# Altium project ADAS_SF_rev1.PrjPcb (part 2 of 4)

## Sheet ADAS_SF_Power_Buck_3V3_1V8_1V1.SchDoc
size 431 x 279 mm; Date: Not shown in title block; ApprovedBy: Not shown in title block; CheckedBy: Not shown in title block; Author: Not shown in title block; CompanyName: Not shown in title block; Engineer: Not shown in title block; Organization: Not shown in title block; Address1: Not shown in title block; Address2: Not shown in title block; Address3: Not shown in title block; Address4: Not shown in title block; DocumentNumber: 1; Revision: Use project parameter SCH_Rev; SheetNumber: 5; SheetTotal: 15; PageSetup: Record=PageOptions¦CenterHorizontal=True¦CenterVertical=True¦PrintScale=1.00¦XCorrection=1.00¦YCorrection=1.00¦PrintKind=0¦BorderSize=5000000¦LeftOffset=0¦BottomOffset=0¦Orientation=2¦PaperLength=1000¦PaperWidth=1000¦Scale=100¦PaperSource=15¦PrintQuality=600¦MediaType=1¦DitherType=10¦PaperKind=Letter¦PrintScaleMode=1
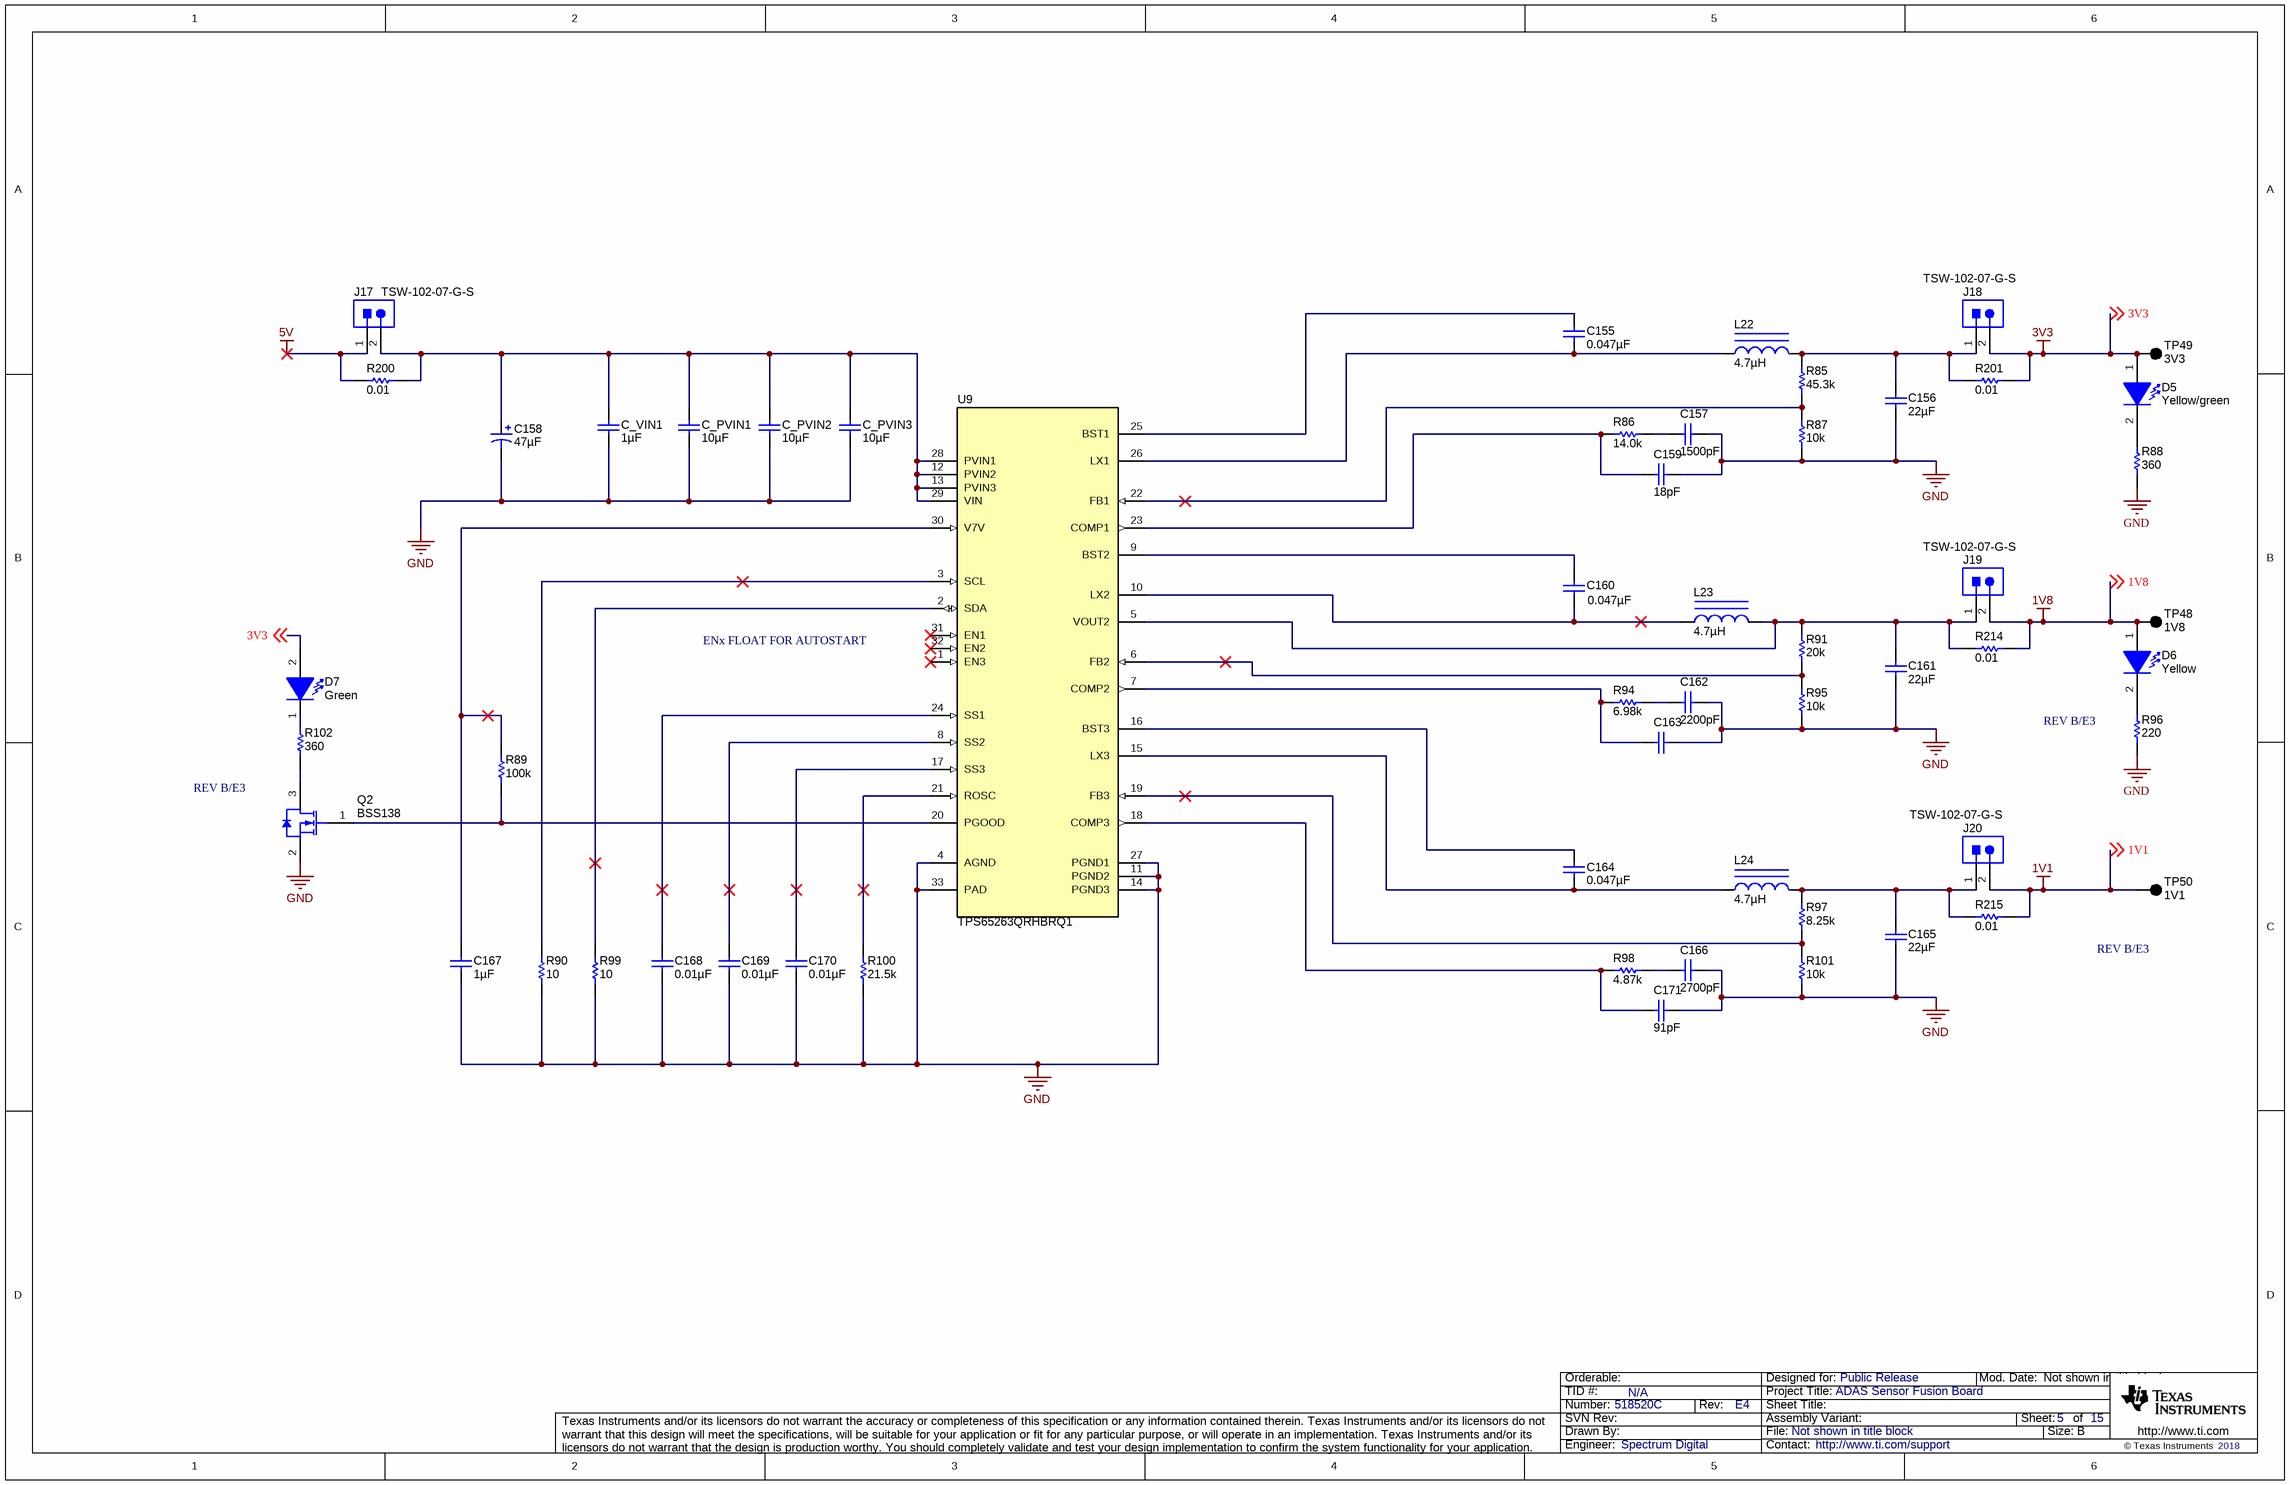
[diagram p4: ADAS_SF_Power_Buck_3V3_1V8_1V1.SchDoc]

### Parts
C155  ValueDisplayed: 0.047µF  [0402]  (hidden comment: GRM155R60J473KA01D)
C156  ValueDisplayed: 22µF  [0603]  (hidden comment: GRM188R61A226ME15D)
C157  ValueDisplayed: 1500pF  [0402]  (hidden comment: GRM155R71H152KA01D)
C158  ValueDisplayed: 47µF  [SM_RADIAL_C]  (hidden comment: EEE-FC0J470R)
C159  ValueDisplayed: 18pF  [0402]  (hidden comment: GRM1555C1H180JA01D)
C160  ValueDisplayed: 0.047µF  [0402]  (hidden comment: GRM155R60J473KA01D)
C161  ValueDisplayed: 22µF  [0603]  (hidden comment: GRM188R61A226ME15D)
C162  ValueDisplayed: 2200pF  [0402]  (hidden comment: GRM155R61A222KA01D)
C163  GRM1555C1H510JA01D  [0402]  (value not drawn)
C164  ValueDisplayed: 0.047µF  [0402]  (hidden comment: GRM155R60J473KA01D)
C165  ValueDisplayed: 22µF  [0603]  (hidden comment: GRM188R61A226ME15D)
C166  ValueDisplayed: 2700pF  [0402]  (hidden comment: GRM155R71H272KA01D)
C167  ValueDisplayed: 1µF  [0402]  (hidden comment: C1005JB1V105K050BC)
C168  ValueDisplayed: 0.01µF  [0402]  (hidden comment: GRM155R71C103KA01D)
C169  ValueDisplayed: 0.01µF  [0402]  (hidden comment: GRM155R71C103KA01D)
C170  ValueDisplayed: 0.01µF  [0402]  (hidden comment: GRM155R71C103KA01D)
C171  ValueDisplayed: 91pF  [0402]  (hidden comment: GRM1555C1H910JA01D)
C_PVIN1  ValueDisplayed: 10µF  [0603]  (hidden comment: GRT188C81A106ME13D)
C_PVIN2  ValueDisplayed: 10µF  [0603]  (hidden comment: GRT188C81A106ME13D)
C_PVIN3  ValueDisplayed: 10µF  [0603]  (hidden comment: GRT188C81A106ME13D)
C_VIN1  ValueDisplayed: 1µF  [0402]  (hidden comment: C1005JB1V105K050BC)
D5  value Yellow/green  [SML-P1_YELLOW-GREEN]  (hidden comment: SML-P12MTT86)
D6  value Yellow  [LED_SMLP12_Yellow]  (hidden comment: SML-P12YTT86)
D7  value Green  [SML-P1_GREEN]  (hidden comment: SML-P12PTT86)
J17  TSW-102-07-G-S  [TSW-102-07-G-S]
J18  TSW-102-07-G-S  [TSW-102-07-G-S]
J19  TSW-102-07-G-S  [TSW-102-07-G-S]
J20  TSW-102-07-G-S  [TSW-102-07-G-S]
L22  ValueDisplayed: 4.7µH  [SDR0805]  (hidden comment: SDR0805-4R7ML)
L23  ValueDisplayed: 4.7µH  [SDR0805]  (hidden comment: SDR0805-4R7ML)
L24  ValueDisplayed: 4.7µH  [SDR0805]  (hidden comment: SDR0805-4R7ML)
Q2  BSS138  [SOT-23]
R85  ValueDisplayed: 45.3k  [0402]  (hidden comment: CRCW040245K3FKED)
R86  ValueDisplayed: 14.0k  [0402]  (hidden comment: CRCW040214K0FKED)
R87  ValueDisplayed: 10k  [0402]  (hidden comment: CRCW040210K0JNED)
R88  ValueDisplayed: 360  [0402]  (hidden comment: CRCW0402360RJNED)
R89  ValueDisplayed: 100k  [0402]  (hidden comment: CRCW0402100KDHEDP)
R90  ValueDisplayed: 10  [0402]  (hidden comment: CRCW040210R0JNED)
R91  ValueDisplayed: 20k  [0402]  (hidden comment: CRCW040220K0JNED)
R94  ValueDisplayed: 6.98k  [0402]  (hidden comment: CRCW04026K98FKED)
R95  ValueDisplayed: 10k  [0402]  (hidden comment: CRCW040210K0JNED)
R96  ValueDisplayed: 220  [0402]  (hidden comment: CRCW0402220RJNED)
R97  ValueDisplayed: 8.25k  [0402]  (hidden comment: CRCW04028K25FKED)
R98  ValueDisplayed: 4.87k  [0402]  (hidden comment: CRCW04024K87FKED)
R99  ValueDisplayed: 10  [0402]  (hidden comment: CRCW040210R0JNED)
R100  ValueDisplayed: 21.5k  [0402]  (hidden comment: CRCW040221K5FKED)
R101  ValueDisplayed: 10k  [0402]  (hidden comment: CRCW040210K0JNED)
R102  ValueDisplayed: 360  [0402]  (hidden comment: CRCW0402360RJNED)
R200  ValueDisplayed: 0.01  [KRL2012]  (hidden comment: KRL2012E-M-R010-F-T5)
R201  ValueDisplayed: 0.01  [KRL2012]  (hidden comment: KRL2012E-M-R010-F-T5)
R214  ValueDisplayed: 0.01  [KRL2012]  (hidden comment: KRL2012E-M-R010-F-T5)
R215  ValueDisplayed: 0.01  [KRL2012]  (hidden comment: KRL2012E-M-R010-F-T5)
TP48  1V8  [Keystone5011]
TP49  3V3  [Keystone5011]
TP50  1V1  [Keystone5011]
U9  TPS65263QRHBRQ1  [RHB0032E]

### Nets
1V1: J20.2 R215.2 TP50.1 ; off-sheet 1V1
1V8: D6.1(A) J19.2 R214.2 TP48.1 ; off-sheet 1V8
3V3: D5.1(A) D7.2(A) J18.2 R201.2 TP49.1 ; off-sheet 3V3
5V: J17.1 R200.1
GND: C156.2 C157.1 C158.2(-) C159.1 C161.2 C162.1 C163.1 C165.2 C166.1 C167.2 C168.2 C169.2 C170.2 C171.1 C_PVIN1.2 C_PVIN2.2 C_PVIN3.2 C_VIN1.2 Q2.2(S) R87.1 R88.2 R90.1 R95.1 R96.1 R99.1 R100.1 R101.1 U9.4(AGND) U9.11(PGND2) U9.14(PGND3) U9.27(PGND1) U9.33(PAD)
NetC155_1: C155.1 U9.25(BST1)
NetC155_2: C155.2 L22.1 U9.26(LX1)
NetC156_1: C156.1 J18.1 L22.2 R85.2 R201.1
NetC157_2: C157.2 R86.2
NetC158_1: C158.1(+) C_PVIN1.1 C_PVIN2.1 C_PVIN3.1 C_VIN1.1 J17.2 R200.2 U9.12(PVIN2) U9.13(PVIN3) U9.28(PVIN1) U9.29(VIN)
NetC159_2: C159.2 R86.1 U9.23(COMP1)
NetC160_1: C160.1 U9.9(BST2)
NetC160_2: C160.2 L23.1 U9.10(LX2)
NetC161_1: C161.1 J19.1 L23.2 R91.2 R214.1 U9.5(VOUT2)
NetC162_2: C162.2 R94.2
NetC163_2: C163.2 R94.1 U9.7(COMP2)
NetC164_1: C164.1 U9.16(BST3)
NetC164_2: C164.2 L24.1 U9.15(LX3)
NetC165_1: C165.1 J20.1 L24.2 R97.2 R215.1
NetC166_2: C166.2 R98.2
NetC167_1: C167.1 R89.2 U9.30(V7V)
NetC168_1: C168.1 U9.24(SS1)
NetC169_1: C169.1 U9.8(SS2)
NetC170_1: C170.1 U9.17(SS3)
NetC171_2: C171.2 R98.1 U9.18(COMP3)
NetD5_2: D5.2(K) R88.1
NetD6_2: D6.2(K) R96.2
NetD7_1: D7.1(K) R102.2
NetQ2_1: Q2.1(G) R89.1 U9.20(PGOOD)
NetQ2_3: Q2.3(D) R102.1
NetR85_1: R85.1 R87.2 U9.22(FB1)
NetR90_2: R90.2 U9.3(SCL)
NetR91_1: R91.1 R95.2 U9.6(FB2)
NetR97_1: R97.1 R101.2 U9.19(FB3)
NetR99_2: R99.2 U9.2(SDA)
NetR100_2: R100.2 U9.21(ROSC)

Not connected (* = marked no-connect by the designer): U9 1(EN3)* 31(EN1)* 32(EN2)*

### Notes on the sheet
- ENx FLOAT FOR AUTOSTART
- REV B/E3

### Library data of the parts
C155 C160 C164 = GRM155R60J473KA01D: CAP, CERM, 0.047 µF, 6.3 V, +/- 10%, X5R, 0402; Manufacturer: MuRata; Polarized: N; CompType: Capacitor; Value: 0.047uF; U/M: EA; Cap_F: 0.000000047; Tolerance_%: 10; Value1: Unknown; VDC_V: 6.3; Value2: 6.3V; TaMin_C: -55; TaMax_C: 85; AEC Category: Q200
C156 C161 C165 = GRM188R61A226ME15D: CAP, CERM, 22 µF, 10 V, +/- 20%, X5R, 0603; Manufacturer: MuRata; Polarized: N; CompType: Capacitor; Value: 22uF; U/M: EA; Cap_F: 0.000022; Tolerance_%: 20; Value1: Unknown; VDC_V: 10; Value2: 10V; TaMin_C: -55; TaMax_C: 85; AEC Category: Q200; SizeArea_mm2: 1.28; SizeAreaWB_mm2: 4.68; SizeX_mm: 1.6; SizeY_mm: 0.8; SizeZ_mm: 1
C157 = GRM155R71H152KA01D: CAP, CERM, 1500 pF, 50 V, +/- 10%, X7R, 0402; Manufacturer: MuRata; Polarized: N; CompType: Capacitor; Value: 1500pF; U/M: EA; Cap_F: 0.0000000015; Tolerance_%: 10; Value1: Unknown; VDC_V: 50; Value2: 50V; TaMin_C: -55; TaMax_C: 125; AEC Category: Q200
C158 = EEE-FC0J470R: CAP, AL, 47 µF, 6.3 V, +/- 20%, 1.8 ohm, SMD; Manufacturer: Panasonic; Polarized: Y; CompType: Capacitor; Value: 47uF; U/M: EA; Cap_F: 0.000047; Tolerance_%: 20; Value1: 1.8 ohm; VDC_V: 6.3; Value2: 6.3V; ESR_ohm: 1.8; IRMS_A: 0.08; TaMin_C: -40; TaMax_C: 105; Cap_Case: C; AEC Category: Q200
C159 = GRM1555C1H180JA01D: CAP, CERM, 18 pF, 50 V, +/- 5%, C0G/NP0, 0402; Manufacturer: MuRata; Polarized: N; CompType: Capacitor; Value: 18pF; U/M: EA; Cap_F: 0.000000000018; Tolerance_%: 5; Value1: Unknown; VDC_V: 50; Value2: 50V; TaMin_C: -55; TaMax_C: 125; AEC Category: Q200
C162 = GRM155R61A222KA01D: CAP, CERM, 2200 pF, 10 V, +/- 10%, X5R, 0402; Manufacturer: MuRata; Polarized: N; CompType: Capacitor; Value: 2200pF; U/M: EA; Cap_F: 0.0000000022; Tolerance_%: 10; Value1: Unknown; Value2: 10V; TaMin_C: -55; TaMax_C: 85; AEC Category: Q200; SizeArea_mm2: 0.5; SizeAreaWB_mm2: 3; SizeX_mm: 1; SizeZ_mm: 0.6
C163 = GRM1555C1H510JA01D: CAP, CERM, 51 pF, 50 V, +/- 5%, C0G/NP0, 0402; Manufacturer: MuRata; Polarized: N; CompType: Capacitor; Value: 51pF; U/M: EA; Cap_F: 0.000000000051; Tolerance_%: 5; Value1: Unknown; VDC_V: 50; Value2: 50V; TaMin_C: -55; TaMax_C: 125; AEC Category: Q200
C166 = GRM155R71H272KA01D: CAP, CERM, 2700 pF, 50 V, +/- 10%, X7R, 0402; Manufacturer: MuRata; Polarized: N; CompType: Capacitor; Value: 2700pF; U/M: EA; Cap_F: 0.0000000027; Tolerance_%: 10; Value1: Unknown; VDC_V: 50; Value2: 50V; TaMin_C: -55; TaMax_C: 125; AEC Category: Q200
C167 C_VIN1 = C1005JB1V105K050BC: CAP, CERM, 1 µF, 35 V, +/- 10%, JB, 0402; Manufacturer: TDK; Polarized: N; CompType: Capacitor; Value: 1uF; U/M: EA; Cap_F: 0.000001; Tolerance_%: 10; Value1: Unknown; VDC_V: 35; Value2: 35V; TaMin_C: -25; TaMax_C: 85; AEC Category: Q200; SizeArea_mm2: 0.5; SizeAreaWB_mm2: 3; SizeX_mm: 1; SizeZ_mm: 0.6
C168-C170 = GRM155R71C103KA01D: Cap, Cer-X7R, 10000pF, 16V, 10%, 0402; Manufacturer: MuRata; Polarized: N; CompType: Capacitor; U/M: EA; Cap_F: 0.00000001; Tolerance_%: 10; Value1: Unknown; VDC_V: 16; TempCo: X7R; TaMin_C: -55; TaMax_C: 125; EN: 102-1-01895; Mfg: MURATA MANUFACTURING CO,LTD; Onhand: 0
C171 = GRM1555C1H910JA01D: CAP, CERM, 91 pF, 50 V, +/- 5%, C0G/NP0, 0402; Manufacturer: MuRata; Polarized: N; CompType: Capacitor; Value: 91pF; U/M: EA; Cap_F: 0.000000000091; Tolerance_%: 5; Value1: Unknown; VDC_V: 50; Value2: 50V; TaMin_C: -55; TaMax_C: 125; AEC Category: Q200
C_PVIN1-C_PVIN3 = GRT188C81A106ME13D: CAP, CERM, 10 µF, 10 V, +/- 20%, X6S, AEC-Q200 Grade 2, 0603; Manufacturer: MuRata; Polarized: N; CompType: Capacitor; Value: 10uF; U/M: EA; Cap_F: 0.00001; Tolerance_%: 20; Value1: Unknown; VDC_V: 10; Value2: 10V; TaMin_C: -55; TaMax_C: 105; AEC Category: Q200; AEC Qualified: Y; AEC Grade: 2; SizeArea_mm2: 1.28; SizeAreaWB_mm2: 4.68; SizeX_mm: 1.6; SizeY_mm: 0.8; SizeZ_mm: 1
D5 = SML-P12MTT86: LED, Yellow/green, SMD; Manufacturer: Rohm; Type: AlInGaP; Vf_V: 2.2; Value2: 2.2V; Io_A: 0.02; Value1: W; U/M: EA
D6 = SML-P12YTT86: LED, Yellow, SMD; Manufacturer: Rohm; Type: InGaN; Vf_V: 2.1; Value2: 2.1V; Io_A: 0.02; Tjmax_C: 85; Value1: W; U/M: EA
D7 = SML-P12PTT86: LED, Green, SMD; Manufacturer: Rohm; Type: AlInGaP; Vf_V: 2.2; Value2: 2.2V; Io_A: 0.02; Value1: W; U/M: EA
J17-J20 = TSW-102-07-G-S: Header, 100mil, 2x1, Gold, TH; Manufacturer: Samtec; SymbolCreator: a0412235; Pitch_mm: 2.54; Gender: Male; Shrouded: N; Row_Count: 1; Current_A: 6.3; Voltage_V: 550; Cert_CSA: Y
L22-L24 = SDR0805-4R7ML: Inductor, Drum Core, Ferrite, 4.7 µH, 3.7 A, 0.03 ohm, SMD; Manufacturer: Bourns; Value: 4.7uH; Ind_H: 4.7E-6; Imax_A: 3.7; Irms: 3.7A @ 40C rise; Isat: 5.37A @ 10% inductance drop; DCR_ohm: 0.03; Value2: 3.7A; AEC Category: Q200
Q2 = BSS138: MOSFET, N-CH, 50 V, 0.22 A, SOT-23; Manufacturer: Fairchild Semiconductor; Alternate Manufacturer: None; U/M: EA; ChType: N; Value: 50V; VdsMax_V: 50; Value1: 6 ohm; Rdson45_ohm: 6; Value2: 1.7 nC; QgTyp_nC: 1.7; Vgs_V: 20; IdsMax_A: 0.22; SizeAreaWB_mm2: 14; SizeArea_mm2: 7.5; SizeX_mm: 2.5; SizeY_mm: 3; SizeZ_mm: 1.1; AEC Category: Q101
R85 = CRCW040245K3FKED: RES, 45.3 k, 1%, 0.063 W, 0402; Manufacturer: Vishay-Dale; CompType: Resistor; Value: 45.3k; Res_ohm: 45300; Value_Code: 45k3; Tolerance_%: 1; Power_W: 0.063; Value2: 0.063W; VDC_V: 50; TempCo: 100 ppm/C; EIA_Code: E96; U/M: EA; AEC Category: Q200
R86 = CRCW040214K0FKED: RES, 14.0 k, 1%, 0.063 W, 0402; Manufacturer: Vishay-Dale; CompType: Resistor; Value: 14.0k; Res_ohm: 14000; Value_Code: 14k0; Tolerance_%: 1; Power_W: 0.063; Value2: 0.063W; VDC_V: 50; TempCo: 100 ppm/C; EIA_Code: E96; U/M: EA; AEC Category: Q200
R87 R95 R101 = CRCW040210K0JNED: RES, 10 k, 5%, 0.063 W, 0402; Manufacturer: Vishay-Dale; CompType: Resistor; Value: 10k; Res_ohm: 10000; Value_Code: 10k0; Tolerance_%: 5; Power_W: 0.063; Value2: 0.063W; VDC_V: 50; TempCo: 200 ppm/C; EIA_Code: E24; U/M: EA; AEC Category: Q200
R88 = CRCW0402360RJNED: RES, 360, 5%, 0.063 W, 0402; Manufacturer: Vishay-Dale; CompType: Resistor; Value: 360; Value_Code: 360R; Tolerance_%: 5; Power_W: 0.063; Value2: 0.063W; VDC_V: 50; TempCo: 200 ppm/C; EIA_Code: E24; U/M: EA
R89 = CRCW0402100KDHEDP: RES, 100 k, 0.5%, 0.063 W, 0402; Manufacturer: Vishay-Dale; CompType: Resistor; Value: 100k; Res_ohm: 100000; Tolerance_%: 0.5; Power_W: 0.063; Value2: 0.063W; VDC_V: 50; TempCo: 50 ppm/C; EIA_Code: E192; U/M: EA; AEC Category: Q200; SizeX_mm: 1; SizeZ_mm: 0.6
R90 = CRCW040210R0JNED: RES, 10, 5%, 0.063 W, 0402; Manufacturer: Vishay-Dale; CompType: Resistor; Value: 10; Value_Code: 10R0; Tolerance_%: 5; Power_W: 0.063; Value2: 0.063W; VDC_V: 50; TempCo: 200 ppm/C; EIA_Code: E24; U/M: EA; AEC Category: Q200; SizeArea_mm2: 0.5; SizeX_mm: 1; SizeZ_mm: 0.6
R91 = CRCW040220K0JNED: RES, 20 k, 5%, 0.063 W, 0402; Manufacturer: Vishay-Dale; CompType: Resistor; Value: 20k; Res_ohm: 20000; Value_Code: 20k0; Tolerance_%: 5; Power_W: 0.063; Value2: 0.063W; VDC_V: 50; TempCo: 200 ppm/C; EIA_Code: E24; U/M: EA; AEC Category: Q200
R94 = CRCW04026K98FKED: RES, 6.98 k, 1%, 0.063 W, 0402; Manufacturer: Vishay-Dale; CompType: Resistor; Value: 6.98k; Res_ohm: 6980; Value_Code: 6k98; Tolerance_%: 1; Power_W: 0.063; Value2: 0.063W; VDC_V: 50; TempCo: 100 ppm/C; EIA_Code: E96; U/M: EA; AEC Category: Q200
R96 = CRCW0402220RJNED: RES, 220, 5%, 0.063 W, 0402; Manufacturer: Vishay-Dale; CompType: Resistor; Value: 220; Value_Code: 220R; Tolerance_%: 5; Power_W: 0.063; Value2: 0.063W; VDC_V: 50; TempCo: 200 ppm/C; EIA_Code: E24; U/M: EA; SizeArea_mm2: 0.5; SizeX_mm: 1; SizeZ_mm: 0.6; AEC Category: Q200
R97 = CRCW04028K25FKED: RES, 8.25 k, 1%, 0.063 W, 0402; Manufacturer: Vishay-Dale; CompType: Resistor; Value: 8.25k; Res_ohm: 8250; Value_Code: 8k25; Tolerance_%: 1; Power_W: 0.063; Value2: 0.063W; VDC_V: 50; TempCo: 100 ppm/C; EIA_Code: E96; U/M: EA; AEC Category: Q200
R98 = CRCW04024K87FKED: RES, 4.87 k, 1%, 0.063 W, 0402; Manufacturer: Vishay-Dale; CompType: Resistor; Value: 4.87k; Res_ohm: 4870; Value_Code: 4k87; Tolerance_%: 1; Power_W: 0.063; Value2: 0.063W; VDC_V: 50; TempCo: 100 ppm/C; EIA_Code: E96; U/M: EA; AEC Category: Q200
R99 = CRCW040210R0JNED: RES, 10, 5%, 0.063 W, 0402; Manufacturer: Vishay-Dale; CompType: Resistor; Value: 10; Value_Code: 10R0; Tolerance_%: 5; Power_W: 0.063; Value2: 0.063W; VDC_V: 50; TempCo: 200 ppm/C; EIA_Code: E24; U/M: EA; AEC Category: Q200
R100 = CRCW040221K5FKED: RES, 21.5 k, 1%, 0.063 W, 0402; Manufacturer: Vishay-Dale; CompType: Resistor; Value: 21.5k; Res_ohm: 21500; Value_Code: 21k5; Tolerance_%: 1; Power_W: 0.063; Value2: 0.063W; VDC_V: 50; TempCo: 100 ppm/C; EIA_Code: E96; U/M: EA; AEC Category: Q200
R102 = CRCW0402360RJNED: RES, 360, 5%, 0.063 W, 0402; Manufacturer: Vishay-Dale; CompType: Resistor; Value: 360; Value_Code: 360R; Tolerance_%: 5; Power_W: 0.063; Value2: 0.063W; VDC_V: 50; TempCo: 200 ppm/C; EIA_Code: E24; U/M: EA; SizeArea_mm2: 0.5; SizeX_mm: 1; SizeZ_mm: 0.6; AEC Category: Q200
R200 R201 R214 R215 = KRL2012E-M-R010-F-T5: RES, 0.01, 1%, 1 W, AEC-Q200 Grade 0, 0508; Manufacturer: Susumu Co Ltd; CompType: Resistor; Value: 0.01; Value_Code: R010; Tolerance_%: 1; Value2: 1W; TempCo: 25 ppm/C; EIA_Code: E96; U/M: EA; AEC Category: Q200; AEC Qualified: Y; AEC Grade: 0
TP48-TP50 = 5011: Test Point, Multipurpose, Black, TH; Manufacturer: Keystone; CompType: Test Point Loop; U/M: EA
U9 = TPS65263RHBR-Q1: 4.5V to 18V Input Voltage, 3A/2A/2A Output Current Step-Down Converter with I2C controlled DVS., RHB0032E (VQFN-32); Alternate PartNumber: TPS65263QRHBTQ1; Manufacturer: Texas Instruments; SymbolCreator: a0411947; SizeArea_mm2: 25; SizeAreaWB_mm2: 49; SizeX_mm: 5; SizeZ_mm: 1; CompType: IC; U/M: EA

## Sheet ADAS_SF_Data_MSP430.SchDoc
size 431 x 279 mm; Date: Not shown in title block; ApprovedBy: Not shown in title block; CheckedBy: Not shown in title block; Author: Not shown in title block; CompanyName: Not shown in title block; Engineer: Not shown in title block; Organization: Not shown in title block; Address1: Not shown in title block; Address2: Not shown in title block; Address3: Not shown in title block; Address4: Not shown in title block; DocumentNumber: 1; Revision: Use project parameter SCH_Rev; SheetNumber: 6; SheetTotal: 15; PageSetup: Record=PageOptions¦CenterHorizontal=True¦CenterVertical=True¦PrintScale=1.00¦XCorrection=1.00¦YCorrection=1.00¦PrintKind=0¦BorderSize=5000000¦LeftOffset=0¦BottomOffset=0¦Orientation=2¦PaperLength=1000¦PaperWidth=1000¦Scale=100¦PaperSource=15¦PrintQuality=600¦MediaType=1¦DitherType=10¦PaperKind=Letter¦PrintScaleMode=1
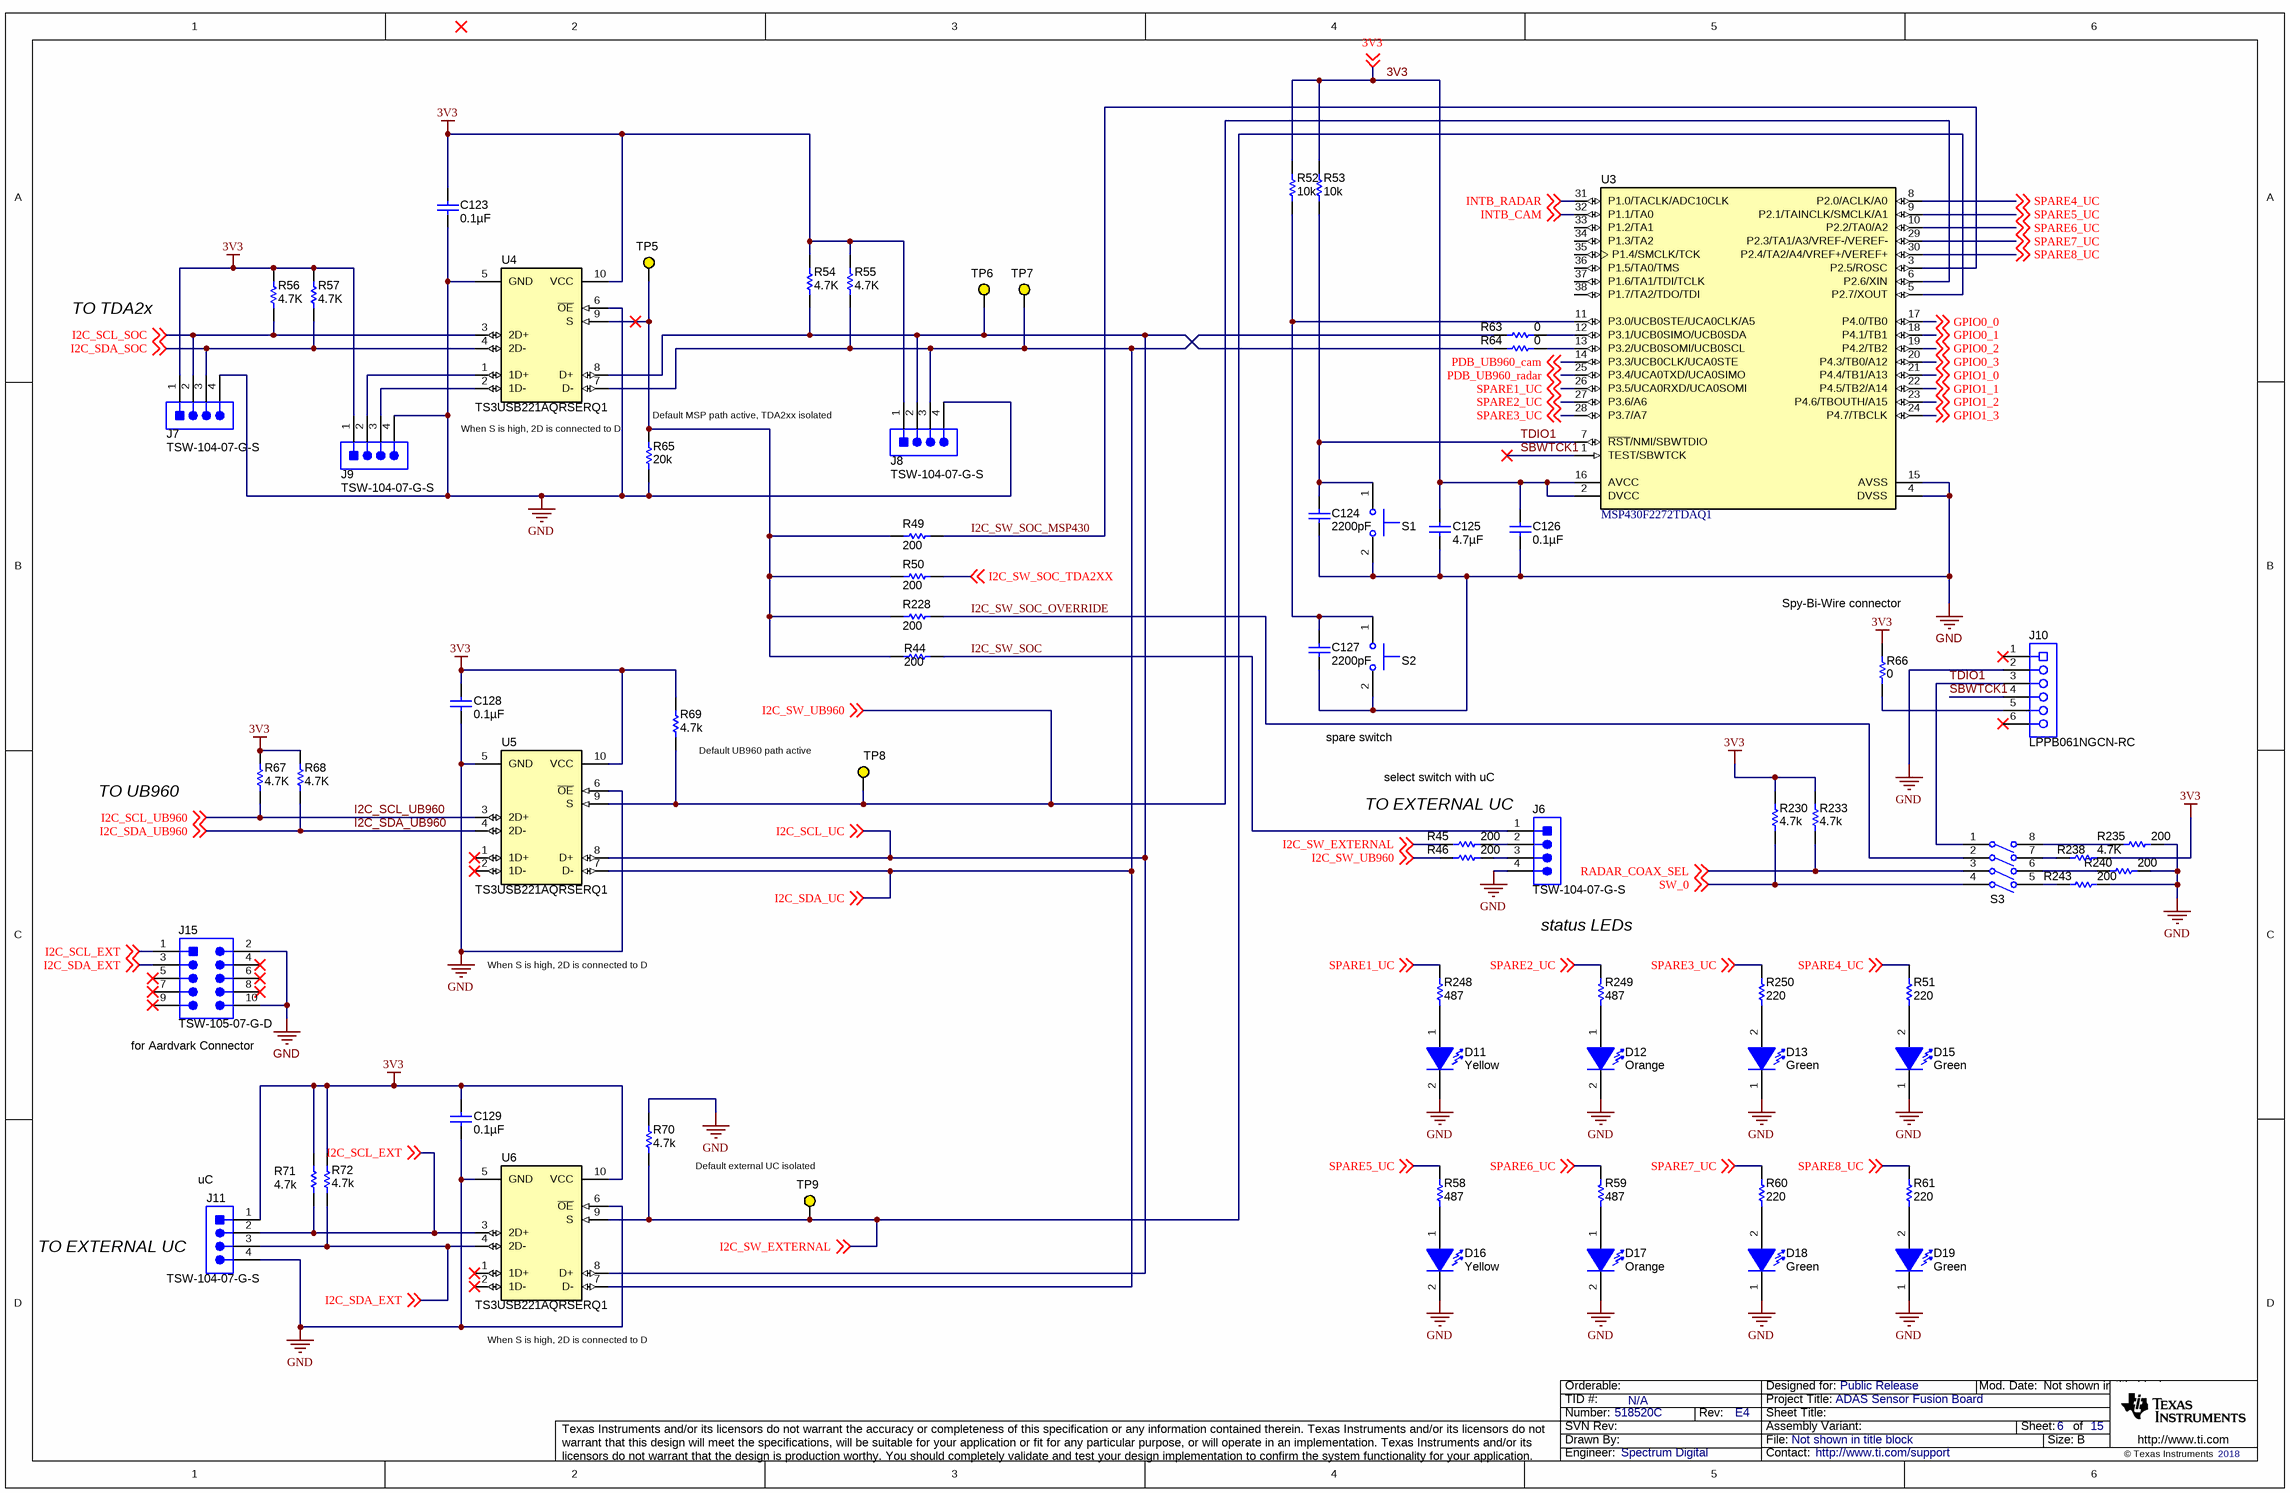
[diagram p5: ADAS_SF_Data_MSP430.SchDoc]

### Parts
C123  ValueDisplayed: 0.1µF  [0603]  (hidden comment: 0603YC104JAT2A)
C124  ValueDisplayed: 2200pF  [0402]  (hidden comment: GRM155R61A222KA01D)
C125  ValueDisplayed: 4.7µF  [0402]  (hidden comment: GRM155R61A475M)
C126  ValueDisplayed: 0.1µF  [0402]  (hidden comment: GCM155R71H104KE02D)
C127  ValueDisplayed: 2200pF  [0402]  (hidden comment: GRM155R61A222KA01D)
C128  ValueDisplayed: 0.1µF  [0603]  (hidden comment: 0603YC104JAT2A)
C129  ValueDisplayed: 0.1µF  [0603]  (hidden comment: 0603YC104JAT2A)
D11  value Yellow  [LED_SMLP12_Yellow]  (hidden comment: SML-P12YTT86)
D12  value Orange  [LED_SMLP12_ORANGE]  (hidden comment: SML-P12DTT86)
D13  value Green  [SML-P1_GREEN]  (hidden comment: SML-P12PTT86)
D15  value Green  [SML-P1_GREEN]  (hidden comment: SML-P12PTT86)
D16  value Yellow  [LED_SMLP12_Yellow]  (hidden comment: SML-P12YTT86)
D17  value Orange  [LED_SMLP12_ORANGE]  (hidden comment: SML-P12DTT86)
D18  value Green  [SML-P1_GREEN]  (hidden comment: SML-P12PTT86)
D19  value Green  [SML-P1_GREEN]  (hidden comment: SML-P12PTT86)
J6  TSW-104-07-G-S  [TSW-104-07-G-S]
J7  TSW-104-07-G-S  [TSW-104-07-G-S]
J8  TSW-104-07-G-S  [TSW-104-07-G-S]
J9  TSW-104-07-G-S  [TSW-104-07-G-S]
J10  LPPB061NGCN-RC  [SULLINS_LPPB061NGCN-RC]
J11  TSW-104-07-G-S  [TSW-104-07-G-S]
J15  TSW-105-07-G-D  [TSW-105-07-G-D]
R44  ValueDisplayed: 200  [0402]  (hidden comment: CRCW0402200RJNED)
R45  ValueDisplayed: 200  [0402]  (hidden comment: CRCW0402200RJNED)
R46  ValueDisplayed: 200  [0402]  (hidden comment: CRCW0402200RJNED)
R49  ValueDisplayed: 200  [0402]  (hidden comment: CRCW0402200RJNED)
R50  ValueDisplayed: 200  [0402]  (hidden comment: CRCW0402200RJNED)
R51  ValueDisplayed: 220  [0402]  (hidden comment: CRCW0402220RJNED)
R52  ValueDisplayed: 10k  [0402]  (hidden comment: CRCW040210K0JNED)
R53  ValueDisplayed: 10k  [0402]  (hidden comment: CRCW040210K0JNED)
R54  value 4.7K  [0402]  (hidden comment: CRCW04024K70JNED)
R55  value 4.7K  [0402]  (hidden comment: CRCW04024K70JNED)
R56  value 4.7K  [0402]  (hidden comment: CRCW04024K70JNED)
R57  value 4.7K  [0402]  (hidden comment: CRCW04024K70JNED)
R58  value 487  [0402]  (hidden comment: CRCW0402487RFKED)
R59  value 487  [0402]  (hidden comment: CRCW0402487RFKED)
R60  ValueDisplayed: 220  [0402]  (hidden comment: CRCW0402220RJNED)
R61  ValueDisplayed: 220  [0402]  (hidden comment: CRCW0402220RJNED)
R63  value 0  [0402]  (hidden comment: CRCW04020000Z0ED)
R64  value 0  [0402]  (hidden comment: CRCW04020000Z0ED)
R65  ValueDisplayed: 20k  [0402]  (hidden comment: CRCW040220K0JNED)
R66  value 0  [0603]  (hidden comment: CRCW06030000Z0EA)
R67  value 4.7K  [0402]  (hidden comment: CRCW04024K70JNED)
R68  value 4.7K  [0402]  (hidden comment: CRCW04024K70JNED)
R69  value 4.7k  [0603]  (hidden comment: CRCW06034K70JNEA)
R70  value 4.7k  [0603]  (hidden comment: CRCW06034K70JNEA)
R71  value 4.7k  [0603]  (hidden comment: CRCW06034K70JNEA)
R72  value 4.7k  [0603]  (hidden comment: CRCW06034K70JNEA)
R228  ValueDisplayed: 200  [0402]  (hidden comment: CRCW0402200RJNED)
R230  value 4.7k  [0603]  (hidden comment: CRCW06034K70JNEA)
R233  value 4.7k  [0603]  (hidden comment: CRCW06034K70JNEA)
R235  ValueDisplayed: 200  [0402]  (hidden comment: CRCW0402200RJNED)
R238  value 4.7K  [0402]  (hidden comment: CRCW04024K70JNED)
R240  ValueDisplayed: 200  [0402]  (hidden comment: CRCW0402200RJNED)
R243  ValueDisplayed: 200  [0402]  (hidden comment: CRCW0402200RJNED)
R248  value 487  [0402]  (hidden comment: CRCW0402487RFKED)
R249  value 487  [0402]  (hidden comment: CRCW0402487RFKED)
R250  ValueDisplayed: 220  [0402]  (hidden comment: CRCW0402220RJNED)
S1  SKRKAEE010  [SW_SKRKAEE010]  (value not drawn)
S2  SKRKAEE010  [SW_SKRKAEE010]  (value not drawn)
S3  218-4LPST  [SW_218-4LPST]  (value not drawn)
TP5  5004  [Keystone5004]  (value not drawn)
TP6  5004  [Keystone5004]  (value not drawn)
TP7  5004  [Keystone5004]  (value not drawn)
TP8  5004  [Keystone5004]  (value not drawn)
TP9  5004  [Keystone5004]  (value not drawn)
U3  MSP430F2272TDAQ1  [DA0038A_N]
U4  TS3USB221AQRSERQ1  [RSE0010A]
U5  TS3USB221AQRSERQ1  [RSE0010A]
U6  TS3USB221AQRSERQ1  [RSE0010A]

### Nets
3V3: C123.1 C125.1 C126.1 C128.1 C129.1 J7.1 J8.1 J9.1 J11.1 R52.2 R53.2 R54.2 R55.2 R56.2 R57.2 R66.2 R67.2 R68.2 R69.1 R71.2 R72.2 R230.1 R233.1 R238.2 U3.2(DVCC) U3.16(AVCC) U4.10(VCC) U5.10(VCC) U6.10(VCC) ; off-sheet 3V3
GND: C123.2 C124.2 C125.2 C126.2 C127.2 C128.2 C129.2 D11.2(K) D12.2(K) D13.1(K) D15.1(K) D16.2(K) D17.2(K) D18.1(K) D19.1(K) J6.4 J7.4 J8.4 J9.4 J10.2 J11.4 J15.2 J15.10 R65.1 R70.2 R235.2 R240.2 R243.2 S1.2 S2.2 U3.4(DVSS) U3.15(AVSS) U4.5(GND) U4.6(~{OE}) U5.5(GND) U5.6(~{OE}) U6.5(GND) U6.6(~{OE})
GPIO0_0: U3.17(P4.0/TB0) ; off-sheet GPIO0_0
GPIO0_1: U3.18(P4.1/TB1) ; off-sheet GPIO0_1
GPIO0_2: U3.19(P4.2/TB2) ; off-sheet GPIO0_2
GPIO0_3: U3.20(P4.3/TB0/A12) ; off-sheet GPIO0_3
GPIO1_0: U3.21(P4.4/TB1/A13) ; off-sheet GPIO1_0
GPIO1_1: U3.22(P4.5/TB2/A14) ; off-sheet GPIO1_1
GPIO1_2: U3.23(P4.6/TBOUTH/A15) ; off-sheet GPIO1_2
GPIO1_3: U3.24(P4.7/TBCLK) ; off-sheet GPIO1_3
I2C_SCL_EXT: J11.2 J15.1 R71.1 U6.3(2D+) ; off-sheet I2C_SCL_EXT
I2C_SCL_SOC: J7.2 R56.1 U4.3(2D+) ; off-sheet I2C_SCL_SOC
I2C_SCL_UB960: R67.1 U5.3(2D+) ; off-sheet I2C_SCL_UB960
I2C_SCL_UC: J8.2 R54.1 R64.1 TP6.1 U4.8(D+) U5.8(D+) U6.8(D+) ; off-sheet I2C_SCL_UC
I2C_SDA_EXT: J11.3 J15.3 R72.1 U6.4(2D-) ; off-sheet I2C_SDA_EXT
I2C_SDA_SOC: J7.3 R57.1 U4.4(2D-) ; off-sheet I2C_SDA_SOC
I2C_SDA_UB960: R68.1 U5.4(2D-) ; off-sheet I2C_SDA_UB960
I2C_SDA_UC: J8.3 R55.1 R63.1 TP7.1 U4.7(D-) U5.7(D-) U6.7(D-) ; off-sheet I2C_SDA_UC
I2C_SW_EXTERNAL: R45.1 R70.1 TP9.1 U3.5(P2.7/XOUT) U6.9(S) ; off-sheet I2C_SW_EXTERNAL
I2C_SW_SOC: J6.1 R44.2
I2C_SW_SOC_MSP430: R49.2 U3.3(P2.5/ROSC)
I2C_SW_SOC_OVERRIDE: R228.2 S3.2(A2)
I2C_SW_SOC_TDA2XX: R50.2 ; off-sheet I2C_SW_SOC_TDA2XX
I2C_SW_UB960: R46.1 R69.2 TP8.1 U3.6(P2.6/XIN) U5.9(S) ; off-sheet I2C_SW_UB960
INTB_CAM: U3.32(P1.1/TA0) ; off-sheet INTB_CAM
INTB_RADAR: U3.31(P1.0/TACLK/ADC10CLK) ; off-sheet INTB_RADAR
PDB_UB960_cam: U3.14(P3.3/UCB0CLK/UCA0STE) ; off-sheet PDB_UB960_cam
PDB_UB960_radar: U3.25(P3.4/UCA0TXD/UCA0SIMO) ; off-sheet PDB_UB960_radar
RADAR_COAX_SEL: R233.2 S3.3(A3) ; off-sheet RADAR_COAX_SEL
SBWTCK1: J10.4 U3.1(TEST/SBWTCK)
SPARE1_UC: R248.2 U3.26(P3.5/UCA0RXD/UCA0SOMI) ; off-sheet SPARE1_UC
SPARE2_UC: R249.2 U3.27(P3.6/A6) ; off-sheet SPARE2_UC
SPARE3_UC: R250.2 U3.28(P3.7/A7) ; off-sheet SPARE3_UC
SPARE4_UC: R51.2 U3.8(P2.0/ACLK/A0) ; off-sheet SPARE4_UC
SPARE5_UC: R58.2 U3.9(P2.1/TAINCLK/SMCLK/A1) ; off-sheet SPARE5_UC
SPARE6_UC: R59.2 U3.10(P2.2/TA0/A2) ; off-sheet SPARE6_UC
SPARE7_UC: R60.2 U3.29(P2.3/TA1/A3/VREF-/VEREF-) ; off-sheet SPARE7_UC
SPARE8_UC: R61.2 U3.30(P2.4/TA2/A4/VREF+/VEREF+) ; off-sheet SPARE8_UC
SW_0: R230.2 S3.4(A4) ; off-sheet SW_0
TDIO1: C124.1 J10.3 R53.1 S1.1 S3.1(A1) U3.7(~{RST}/NMI/SBWTDIO)
NetC127_1: C127.1 R52.1 S2.1 U3.11(P3.0/UCB0STE/UCA0CLK/A5)
NetD11_1: D11.1(A) R248.1
NetD12_1: D12.1(A) R249.1
NetD13_2: D13.2(A) R250.1
NetD15_2: D15.2(A) R51.1
NetD16_1: D16.1(A) R58.1
NetD17_1: D17.1(A) R59.1
NetD18_2: D18.2(A) R60.1
NetD19_2: D19.2(A) R61.1
NetJ6_2: J6.2 R45.2
NetJ6_3: J6.3 R46.2
NetJ9_2: J9.2 U4.1(1D+)
NetJ9_3: J9.3 U4.2(1D-)
NetJ10_5: J10.5 R66.1
NetR44_1: R44.1 R49.1 R50.1 R65.2 R228.1 TP5.1 U4.9(S)
NetR63_2: R63.2 U3.12(P3.1/UCB0SIMO/UCB0SDA)
NetR64_2: R64.2 U3.13(P3.2/UCB0SOMI/UCB0SCL)
NetR235_1: R235.1 S3.8(B1)
NetR238_1: R238.1 S3.7(B2)
NetR240_1: R240.1 S3.6(B3)
NetR243_1: R243.1 S3.5(B4)

Not connected (* = marked no-connect by the designer): J10 1* 6*; J15 4* 5* 6* 7* 8* 9*; U3 33(P1.2/TA1) 34(P1.3/TA2) 35(P1.4/SMCLK/TCK) 36(P1.5/TA0/TMS) 37(P1.6/TA1/TDI/TCLK) 38(P1.7/TA2/TDO/TDI); U5 1(1D+)* 2(1D-)*; U6 1(1D+)* 2(1D-)*

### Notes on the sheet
- TO TDA2x
- When S is high, 2D is connected to D
- (near R65) Default MSP path active, TDA2xx isolated
- (near R66) Spy-Bi-Wire connector
- (near R69) Default UB960 path active
- spare switch
- select switch with uC
- TO UB960
- TO EXTERNAL UC
- status LEDs
- (near J15) for Aardvark Connector
- (near J11) uC
- Default external UC isolated
- (near U6) When S is high, 2D is connected to D

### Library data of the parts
C123 C128 C129 = 0603YC104JAT2A: CAP, CERM, 0.1uF, 16V, +/-5%, X7R, 0603; Manufacturer: AVX; Polarized: N; CompType: Capacitor; U/M: EA; Cap_F: 0.0000001; Tolerance_%: 5; ESR_Ohm: 0.039; Value1: 0.039 ohm; VDC_V: 16; TaMin_C: -55; TaMax_C: 125
C124 C127 = GRM155R61A222KA01D: CAP, CERM, 2200 pF, 10 V, +/- 10%, X5R, 0402; Manufacturer: MuRata; Polarized: N; CompType: Capacitor; Value: 2200pF; U/M: EA; Cap_F: 0.0000000022; Tolerance_%: 10; Value1: Unknown; Value2: 10V; TaMin_C: -55; TaMax_C: 85; AEC Category: Q200
C125 = GRM155R61A475M: CAP, CERM, 4.7 µF, 10 V, +/- 20%, X5R, 0402; Manufacturer: MuRata; Polarized: N; CompType: Capacitor; Value: 4.7uF; U/M: EA; Cap_F: 0.0000047; Tolerance_%: 20; Value1: Unknown; VDC_V: 10; Value2: 10V; TaMin_C: -55; TaMax_C: 85; AEC Category: Q200
C126 = GCM155R71H104KE02D: CAP, CERM, 0.1 µF, 50 V, +/- 10%, X7R, AEC-Q200 Grade 1, 0402; Manufacturer: MuRata; Polarized: N; CompType: Capacitor; Value: 0.1uF; U/M: EA; Cap_F: 0.0000001; Tolerance_%: 10; Value1: Unknown; VDC_V: 50; Value2: 50V; TaMin_C: -55; TaMax_C: 125; AEC Category: Q200; AEC Qualified: Y; AEC Grade: 1; SizeArea_mm2: 0.5; SizeAreaWB_mm2: 3; SizeZ_mm: 0.6
D11 D16 = SML-P12YTT86: as D6 on sheet ADAS_SF_Power_Buck_3V3_1V8_1V1
D12 D17 = SML-P12DTT86: LED, Orange, SMD; Manufacturer: Rohm; Type: InGaN; Vf_V: 2.1; Value2: 2.1V; Io_A: 0.02; Tjmax_C: 85; Value1: W; U/M: EA
D13 D15 D18 D19 = SML-P12PTT86: as D7 on sheet ADAS_SF_Power_Buck_3V3_1V8_1V1
J6-J9 J11 = TSW-104-07-G-S: Header, 100mil, 4x1, Gold, TH; Manufacturer: Samtec; SymbolCreator: a0412235; U/M: EA
J10 = LPPB061NGCN-RC: Receptacle, 50mil, 6x1, Gold, R/A, TH; Manufacturer: Sullins Connector Solutions; SymbolCreator: a0411947
J15 = TSW-105-07-G-D: Header, 100mil, 5x2, Gold, TH; Manufacturer: Samtec; SymbolCreator: a0412235; U/M: EA
R44-R46 R235 R240 R243 = CRCW0402200RJNED: RES, 200, 5%, 0.063 W, 0402; Manufacturer: Vishay-Dale; CompType: Resistor; Value: 200; Value_Code: 200R; Tolerance_%: 5; Power_W: 0.063; Value2: 0.063W; VDC_V: 50; TempCo: 200 ppm/C; EIA_Code: E24; U/M: EA
R49 R50 R228 = CRCW0402200RJNED: RES, 200, 5%, 0.063 W, 0402; Manufacturer: Vishay-Dale; CompType: Resistor; Value: 200; Value_Code: 200R; Tolerance_%: 5; Power_W: 0.063; Value2: 0.063W; VDC_V: 50; TempCo: 200 ppm/C; EIA_Code: E24; U/M: EA; SizeArea_mm2: 0.5; SizeX_mm: 1; SizeZ_mm: 0.6; AEC Category: Q200
R51 R60 R61 R250 = CRCW0402220RJNED: RES, 220, 5%, 0.063 W, 0402; Manufacturer: Vishay-Dale; CompType: Resistor; Value: 220; Value_Code: 220R; Tolerance_%: 5; Power_W: 0.063; Value2: 0.063W; VDC_V: 50; TempCo: 200 ppm/C; EIA_Code: E24; U/M: EA
R52 R53 = CRCW040210K0JNED: as R87 on sheet ADAS_SF_Power_Buck_3V3_1V8_1V1
R54-R57 R67 R68 R238 = CRCW04024K70JNED: Res, Chip, 4.7K, 1/16W, 5%, 0402; Manufacturer: Vishay-Dale; PART Name: SCH_LIB\RES; CompType: Resistor; Res_ohm: 4700; Value_Code: 4k70; Tolerance_%: 5; Power_W: 0.063; Value2: 0.063W; VDC_V: 50; TempCo: 200 ppm/C; EIA_Code: E24; U/M: EA; DECAL Name: 0402,0402_HD; EN: 101-1-02785; Mfg: VISHAY; Onhand: 6860
R58 R59 R248 R249 = CRCW0402487RFKED: RES, 487 ohm, 1%, 0.063W, 0402; Manufacturer: Vishay-Dale; Alternate Manufacturer: Any; Alternate PartNumber: Equivalent; CompType: Resistor; Value_Code: 487R; Tolerance_%: 1; Power_W: 0.063; VDC_V: 50; TempCo: 100 ppm/C; EIA_Code: E96; U/M: EA
R63 R64 = CRCW04020000Z0ED: RES, 0 ohm, 5%, 0.063W, 0402; Manufacturer: Vishay-Dale; CompType: Resistor; Value_Code: 0000; Tolerance_%: 5; Power_W: 0.063; VDC_V: 50; TempCo: 200 ppm/C; EIA_Code: E24; U/M: EA; EN: 101-1-00001
R65 = CRCW040220K0JNED: as R91 on sheet ADAS_SF_Power_Buck_3V3_1V8_1V1
R66 = CRCW06030000Z0EA: RES, 0 ohm, 5%, 0.1W, 0603; Manufacturer: Vishay-Dale; CompType: Resistor; Value_Code: 0000; Tolerance_%: 5; Power_W: 0.1; VDC_V: 75; TempCo: 200 ppm/C; EIA_Code: E24; U/M: EA; EN: 101-1-03483
R69-R72 R230 R233 = CRCW06034K70JNEA: RES, 4.7k ohm, 5%, 0.1W, 0603; Manufacturer: Vishay-Dale; CompType: Resistor; Res_ohm: 4700; Value_Code: 4k70; Tolerance_%: 5; Power_W: 0.1; VDC_V: 75; TempCo: 200 ppm/C; EIA_Code: E24; U/M: EA
S1 S2 = SKRKAEE010: Switch, Push Button, SMD; Manufacturer: Alps; SymbolCreator: a0412235; Circuit: SPST-NO; VDC_V: 12; SwitchFunction: Off-Mom; PositionCount: 1; CurrentRating_mA: 50
S3 = 218-4LPST: Switch, Slide, SPST 4 poles, SMT; Manufacturer: CTS Electrocomponents; SymbolCreator: a0412235; VDC_V: 24; SwitchFunction: Off-On; PositionCount: 4; CurrentRating_mA: 25
TP5-TP9 = 5004: Test Point, Miniature, Yellow, TH; Manufacturer: Keystone; CompType: Test Point Loop; U/M: EA
U3 = MSP430F2272TDAQ1: 16 MHz Mixed Signal Microcontroller with 32 KB Flash, 1024 B SARM and 32 GPIOs, -40 to 105 degC, 38-pin SOP (DA); Alternate Manufacturer: Texas Instruments; Alternate PartNumber: Equivalent; ADC: 10-bit SAR; ADC Channels: 12; Brown Out Reset: Yes; Eco-Plan: TBD; Flash(KB): 32; Frequency(MHz): 16; Pin/Package: 38TSSOP, 40VQFN; SRAM(B): 1024; SubFamily: Automotive, Extended Temp; Timers - 16-bit: 2; USCI_A (UART/LIN/IrDA/SPI): 1
U4-U6 = TS3USB221AQRSERQ1: Automotive Catalog ESD Protected, High-Speed USB 2.0 (480-Mbps) 1:2 Multiplexer / Demultiplexer Switch, 16 ohm RON, 2.5 to 3.3V, -40 to 125 degC, 10-Pin UQFN (RSE), Green (RoHS & no Sb/Br); Manufacturer: Texas Instruments; Alternate PartNumber: Equivalent; SubFamily: USB Switch; Number of Channels: 2; Architecture: 1; ESD HBM(kV): +/-7; ICC(uA): 30; tpd max(ns): 0.25; ron(max)(ohms): 16; RON Mis-match(Max)(Ohms): 0.2; Bandwidth(MHz): 900; ON Time(Max)(ns): 12

## Sheet ADAS_SF_Data_Deserializer_Camera.SchDoc
size 431 x 279 mm; Date: Not shown in title block; ApprovedBy: Not shown in title block; CheckedBy: Not shown in title block; Author: Not shown in title block; CompanyName: Not shown in title block; Engineer: Not shown in title block; Organization: Not shown in title block; Address1: Not shown in title block; Address2: Not shown in title block; Address3: Not shown in title block; Address4: Not shown in title block; DocumentNumber: 1; Revision: Use project parameter SCH_Rev; SheetNumber: 7; SheetTotal: 15; PageSetup: Record=PageOptions¦CenterHorizontal=True¦CenterVertical=True¦PrintScale=1.00¦XCorrection=1.00¦YCorrection=1.00¦PrintKind=0¦BorderSize=5000000¦LeftOffset=0¦BottomOffset=0¦Orientation=2¦PaperLength=1000¦PaperWidth=1000¦Scale=100¦PaperSource=15¦PrintQuality=600¦MediaType=1¦DitherType=10¦PaperKind=Letter¦PrintScaleMode=1
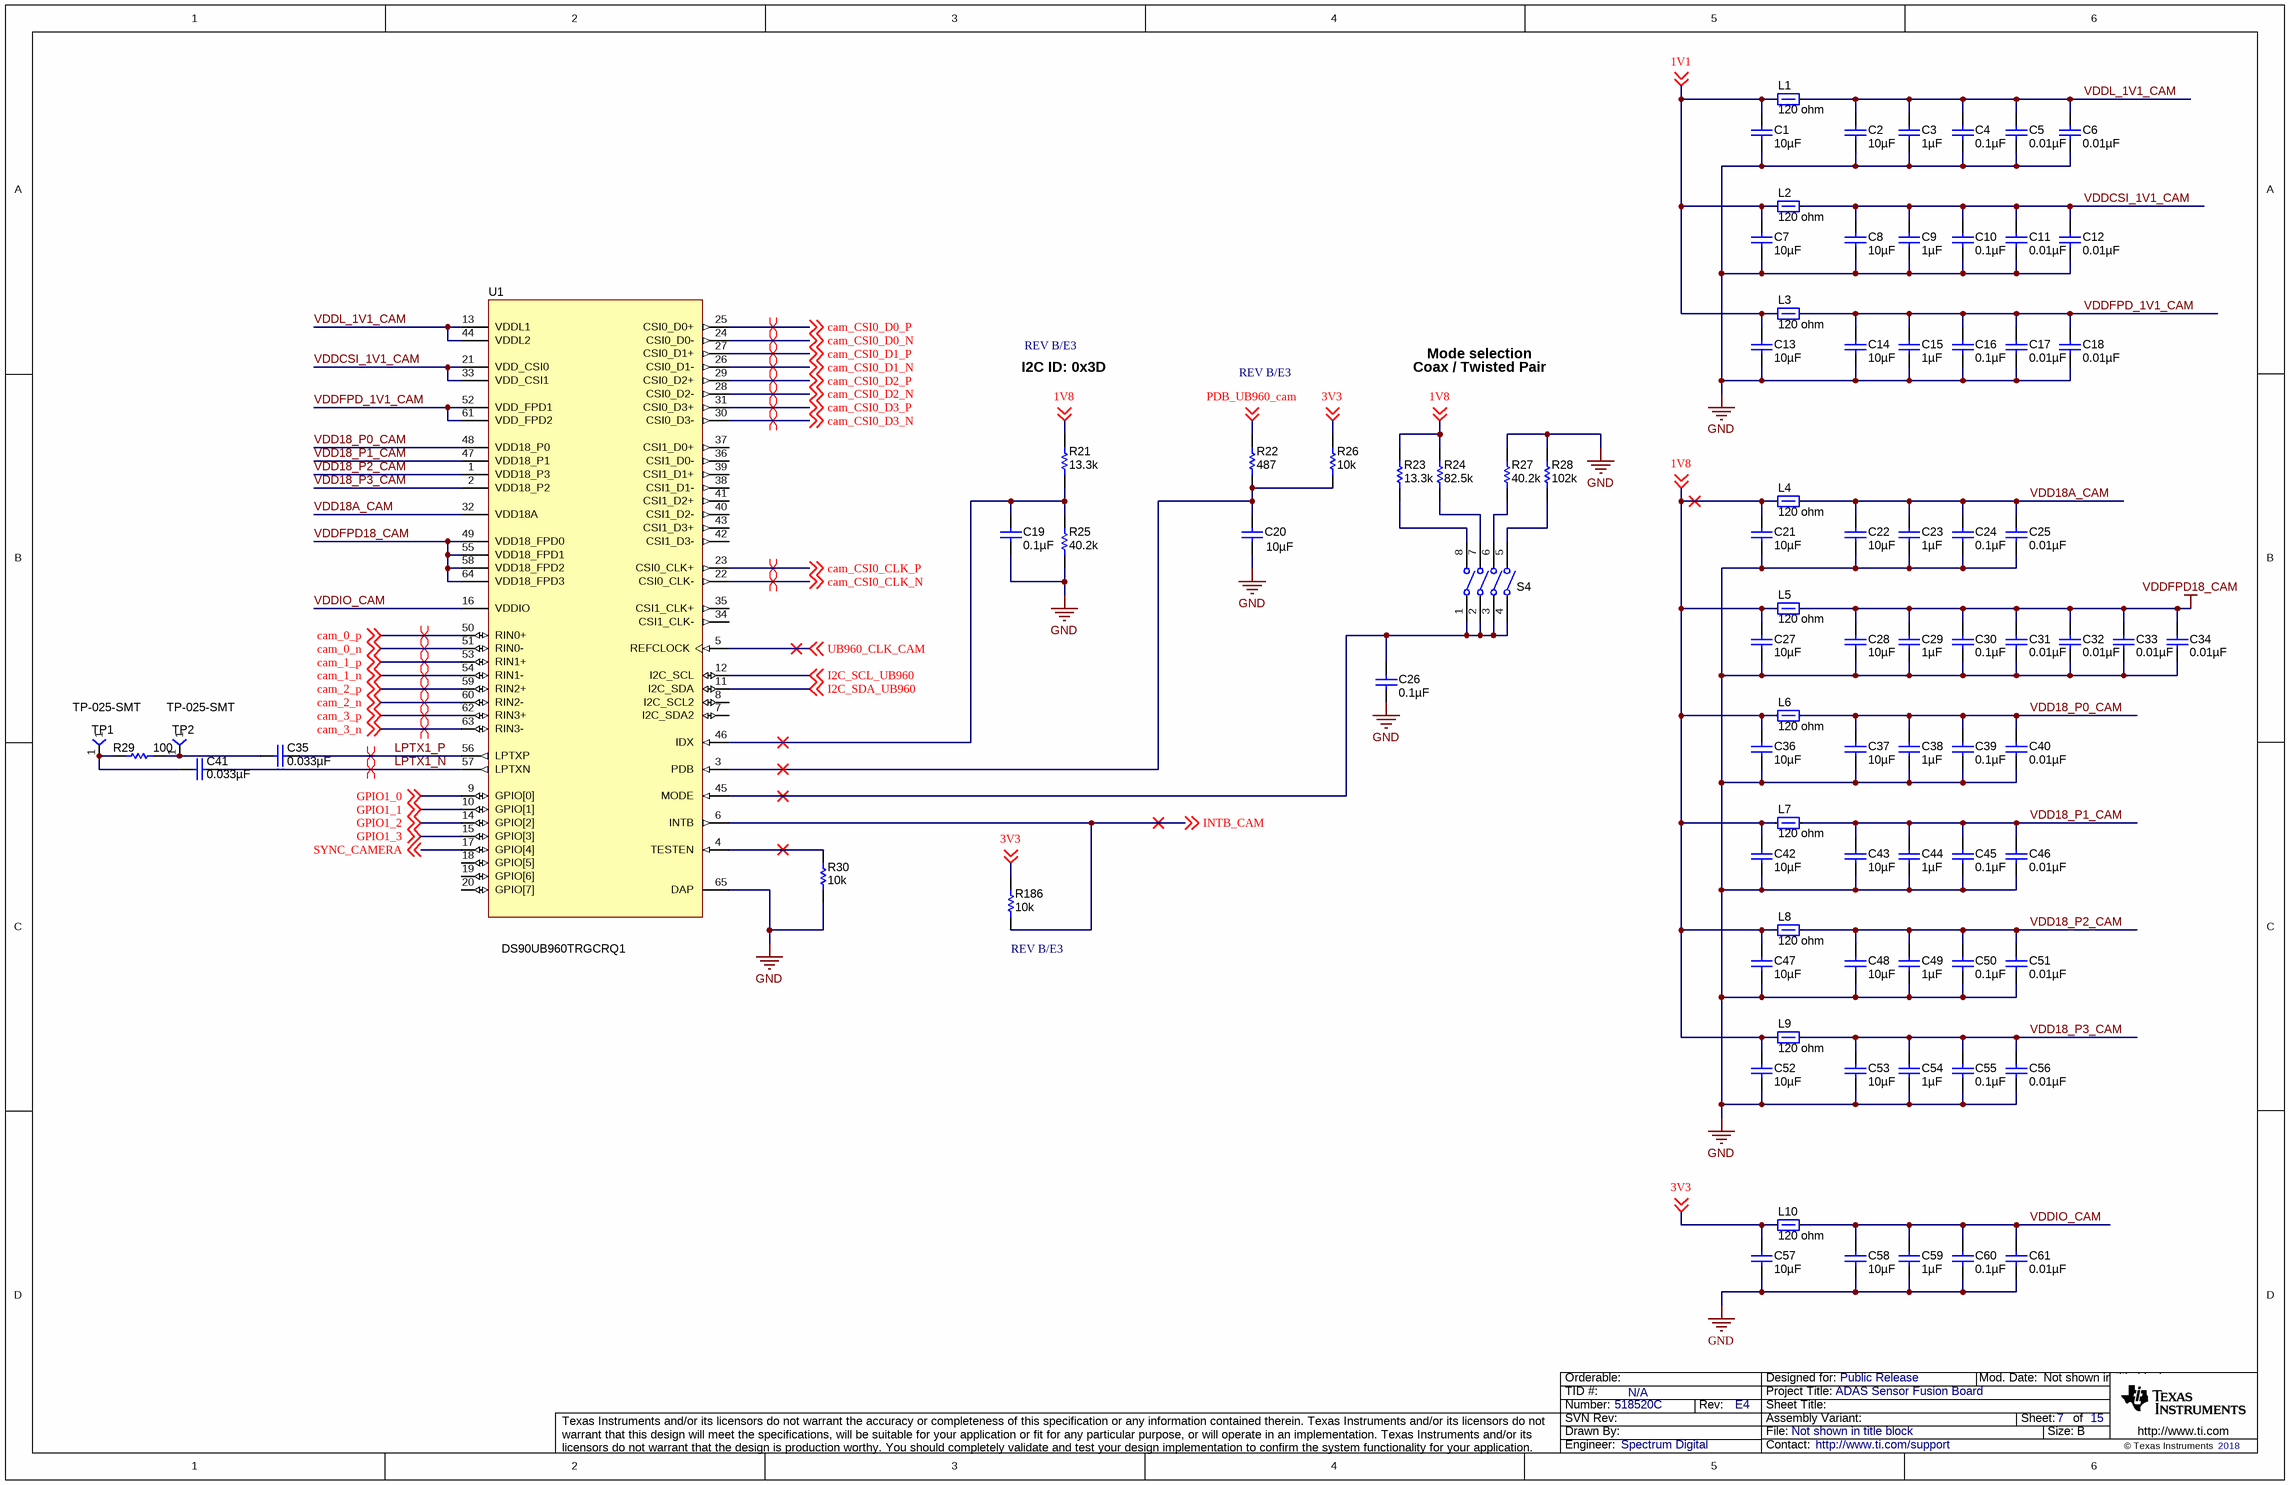
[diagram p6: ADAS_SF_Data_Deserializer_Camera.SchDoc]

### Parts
C1  ValueDisplayed: 10µF  [0805_HV]  (hidden comment: CL21A106KAFN3NE)
C2  ValueDisplayed: 10µF  [0805_HV]  (hidden comment: CL21A106KAFN3NE)
C3  ValueDisplayed: 1µF  [0402]  (hidden comment: C1005JB1V105K050BC)
C4  ValueDisplayed: 0.1µF  [0402]  (hidden comment: GCM155R71H104KE02D)
C5  ValueDisplayed: 0.01µF  [0402]  (hidden comment: GCM155R71H103KA55D)
C6  ValueDisplayed: 0.01µF  [0402]  (hidden comment: GCM155R71H103KA55D)
C7  ValueDisplayed: 10µF  [0805_HV]  (hidden comment: CL21A106KAFN3NE)
C8  ValueDisplayed: 10µF  [0805_HV]  (hidden comment: CL21A106KAFN3NE)
C9  ValueDisplayed: 1µF  [0402]  (hidden comment: C1005JB1V105K050BC)
C10  ValueDisplayed: 0.1µF  [0402]  (hidden comment: GCM155R71H104KE02D)
C11  ValueDisplayed: 0.01µF  [0402]  (hidden comment: GCM155R71H103KA55D)
C12  ValueDisplayed: 0.01µF  [0402]  (hidden comment: GCM155R71H103KA55D)
C13  ValueDisplayed: 10µF  [0805_HV]  (hidden comment: CL21A106KAFN3NE)
C14  ValueDisplayed: 10µF  [0805_HV]  (hidden comment: CL21A106KAFN3NE)
C15  ValueDisplayed: 1µF  [0402]  (hidden comment: C1005JB1V105K050BC)
C16  ValueDisplayed: 0.1µF  [0402]  (hidden comment: GCM155R71H104KE02D)
C17  ValueDisplayed: 0.01µF  [0402]  (hidden comment: GCM155R71H103KA55D)
C18  ValueDisplayed: 0.01µF  [0402]  (hidden comment: GCM155R71H103KA55D)
C19  ValueDisplayed: 0.1µF  [0402]  (hidden comment: GCM155R71H104KE02D)
C20  ValueDisplayed: 10µF  [0805_HV]  (hidden comment: CL21A106KAFN3NE)
C21  ValueDisplayed: 10µF  [0805_HV]  (hidden comment: CL21A106KAFN3NE)
C22  ValueDisplayed: 10µF  [0805_HV]  (hidden comment: CL21A106KAFN3NE)
C23  ValueDisplayed: 1µF  [0402]  (hidden comment: C1005JB1V105K050BC)
C24  ValueDisplayed: 0.1µF  [0402]  (hidden comment: GCM155R71H104KE02D)
C25  ValueDisplayed: 0.01µF  [0402]  (hidden comment: GCM155R71H103KA55D)
C26  ValueDisplayed: 0.1µF  [0402]  (hidden comment: GCM155R71H104KE02D)
C27  ValueDisplayed: 10µF  [0805_HV]  (hidden comment: CL21A106KAFN3NE)
C28  ValueDisplayed: 10µF  [0805_HV]  (hidden comment: CL21A106KAFN3NE)
C29  ValueDisplayed: 1µF  [0402]  (hidden comment: C1005JB1V105K050BC)
C30  ValueDisplayed: 0.1µF  [0402]  (hidden comment: GCM155R71H104KE02D)
C31  ValueDisplayed: 0.01µF  [0402]  (hidden comment: GCM155R71H103KA55D)
C32  ValueDisplayed: 0.01µF  [0402]  (hidden comment: GCM155R71H103KA55D)
C33  ValueDisplayed: 0.01µF  [0402]  (hidden comment: GCM155R71H103KA55D)
C34  ValueDisplayed: 0.01µF  [0402]  (hidden comment: GCM155R71H103KA55D)
C35  ValueDisplayed: 0.033µF  [0402]  (hidden comment: CGA2B3X7R1H333K050BB)
C36  ValueDisplayed: 10µF  [0805_HV]  (hidden comment: CL21A106KAFN3NE)
C37  ValueDisplayed: 10µF  [0805_HV]  (hidden comment: CL21A106KAFN3NE)
C38  ValueDisplayed: 1µF  [0402]  (hidden comment: C1005JB1V105K050BC)
C39  ValueDisplayed: 0.1µF  [0402]  (hidden comment: GCM155R71H104KE02D)
C40  ValueDisplayed: 0.01µF  [0402]  (hidden comment: GCM155R71H103KA55D)
C41  ValueDisplayed: 0.033µF  [0402]  (hidden comment: CGA2B3X7R1H333K050BB)
C42  ValueDisplayed: 10µF  [0805_HV]  (hidden comment: CL21A106KAFN3NE)
C43  ValueDisplayed: 10µF  [0805_HV]  (hidden comment: CL21A106KAFN3NE)
C44  ValueDisplayed: 1µF  [0402]  (hidden comment: C1005JB1V105K050BC)
C45  ValueDisplayed: 0.1µF  [0402]  (hidden comment: GCM155R71H104KE02D)
C46  ValueDisplayed: 0.01µF  [0402]  (hidden comment: GCM155R71H103KA55D)
C47  ValueDisplayed: 10µF  [0805_HV]  (hidden comment: CL21A106KAFN3NE)
C48  ValueDisplayed: 10µF  [0805_HV]  (hidden comment: CL21A106KAFN3NE)
C49  ValueDisplayed: 1µF  [0402]  (hidden comment: C1005JB1V105K050BC)
C50  ValueDisplayed: 0.1µF  [0402]  (hidden comment: GCM155R71H104KE02D)
C51  ValueDisplayed: 0.01µF  [0402]  (hidden comment: GCM155R71H103KA55D)
C52  ValueDisplayed: 10µF  [0805_HV]  (hidden comment: CL21A106KAFN3NE)
C53  ValueDisplayed: 10µF  [0805_HV]  (hidden comment: CL21A106KAFN3NE)
C54  ValueDisplayed: 1µF  [0402]  (hidden comment: C1005JB1V105K050BC)
C55  ValueDisplayed: 0.1µF  [0402]  (hidden comment: GCM155R71H104KE02D)
C56  ValueDisplayed: 0.01µF  [0402]  (hidden comment: GCM155R71H103KA55D)
C57  ValueDisplayed: 10µF  [0805_HV]  (hidden comment: CL21A106KAFN3NE)
C58  ValueDisplayed: 10µF  [0805_HV]  (hidden comment: CL21A106KAFN3NE)
C59  ValueDisplayed: 1µF  [0402]  (hidden comment: C1005JB1V105K050BC)
C60  ValueDisplayed: 0.1µF  [0402]  (hidden comment: GCM155R71H104KE02D)
C61  ValueDisplayed: 0.01µF  [0402]  (hidden comment: GCM155R71H103KA55D)
L1  value 120 ohm  [0603]  (hidden comment: BLM18SG121TN1D)
L2  value 120 ohm  [0603]  (hidden comment: BLM18SG121TN1D)
L3  value 120 ohm  [0603]  (hidden comment: BLM18SG121TN1D)
L4  value 120 ohm  [0603]  (hidden comment: BLM18SG121TN1D)
L5  value 120 ohm  [0603]  (hidden comment: BLM18SG121TN1D)
L6  value 120 ohm  [0603]  (hidden comment: BLM18SG121TN1D)
L7  value 120 ohm  [0603]  (hidden comment: BLM18SG121TN1D)
L8  value 120 ohm  [0603]  (hidden comment: BLM18SG121TN1D)
L9  value 120 ohm  [0603]  (hidden comment: BLM18SG121TN1D)
L10  value 120 ohm  [0603]  (hidden comment: BLM18SG121TN1D)
R21  ValueDisplayed: 13.3k  [0402]  (hidden comment: CRCW040213K3FKED)
R22  ValueDisplayed: 487  [0402]  (hidden comment: CRCW0402487RFKED)
R23  ValueDisplayed: 13.3k  [0402]  (hidden comment: CRCW040213K3FKED)
R24  ValueDisplayed: 82.5k  [0402]  (hidden comment: CRCW040282K5FKED)
R25  ValueDisplayed: 40.2k  [0402]  (hidden comment: CRCW040240K2FKED)
R26  ValueDisplayed: 10k  [0402]  (hidden comment: CRCW040210K0JNED)
R27  ValueDisplayed: 40.2k  [0402]  (hidden comment: CRCW040240K2FKED)
R28  ValueDisplayed: 102k  [0402]  (hidden comment: CRCW0402102KFKED)
R29  ValueDisplayed: 100  [0402]  (hidden comment: CRCW0402100RFKED)
R30  ValueDisplayed: 10k  [0402]  (hidden comment: CRCW040210K0JNED)
R186  ValueDisplayed: 10k  [0402]  (hidden comment: CRCW040210K0JNED)
S4  218-4LPST  [SW_218-4LPST]  (value not drawn)
TP1  TP-025-SMT  [TP_25MIL-SMT]
TP2  TP-025-SMT  [TP_25MIL-SMT]
U1  DS90UB960TRGCRQ1  [RGC0064G]

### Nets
1V1: C1.1 C7.1 C13.1 L1.1 L2.1 L3.1 ; off-sheet 1V1
1V8: C21.1 C27.1 C36.1 C42.1 C47.1 C52.1 L4.1 L5.1 L6.1 L7.1 L8.1 L9.1 R21.2 R23.2 R24.2 ; off-sheet 1V8
3V3: C57.1 L10.1 R26.2 R186.2 ; off-sheet 3V3
GND: C1.2 C2.2 C3.2 C4.2 C5.2 C6.2 C7.2 C8.2 C9.2 C10.2 C11.2 C12.2 C13.2 C14.2 C15.2 C16.2 C17.2 C18.2 C19.2 C20.2 C21.2 C22.2 C23.2 C24.2 C25.2 C26.2 C27.2 C28.2 C29.2 C30.2 C31.2 C32.2 C33.2 C34.2 C36.2 C37.2 C38.2 C39.2 C40.2 C42.2 C43.2 C44.2 C45.2 C46.2 C47.2 C48.2 C49.2 C50.2 C51.2 C52.2 C53.2 C54.2 C55.2 C56.2 C57.2 C58.2 C59.2 C60.2 C61.2 R25.1 R27.2 R28.2 R30.1 U1.65(DAP)
VDDFPD18_CAM: C28.1 C29.1 C30.1 C31.1 C32.1 C33.1 C34.1 L5.2 U1.49(VDD18_FPD0) U1.55(VDD18_FPD1) U1.58(VDD18_FPD2) U1.64(VDD18_FPD3)
cam_0_n: U1.51(RIN0-) ; off-sheet cam_0_n
cam_0_p: U1.50(RIN0+) ; off-sheet cam_0_p
cam_1_n: U1.54(RIN1-) ; off-sheet cam_1_n
cam_1_p: U1.53(RIN1+) ; off-sheet cam_1_p
cam_2_n: U1.60(RIN2-) ; off-sheet cam_2_n
cam_2_p: U1.59(RIN2+) ; off-sheet cam_2_p
cam_3_n: U1.63(RIN3-) ; off-sheet cam_3_n
cam_3_p: U1.62(RIN3+) ; off-sheet cam_3_p
cam_CSI0_CLK_N: U1.22(CSI0_CLK-) ; off-sheet cam_CSI0_CLK_N
cam_CSI0_CLK_P: U1.23(CSI0_CLK+) ; off-sheet cam_CSI0_CLK_P
cam_CSI0_D0_N: U1.24(CSI0_D0-) ; off-sheet cam_CSI0_D0_N
cam_CSI0_D0_P: U1.25(CSI0_D0+) ; off-sheet cam_CSI0_D0_P
cam_CSI0_D1_N: U1.26(CSI0_D1-) ; off-sheet cam_CSI0_D1_N
cam_CSI0_D1_P: U1.27(CSI0_D1+) ; off-sheet cam_CSI0_D1_P
cam_CSI0_D2_N: U1.28(CSI0_D2-) ; off-sheet cam_CSI0_D2_N
cam_CSI0_D2_P: U1.29(CSI0_D2+) ; off-sheet cam_CSI0_D2_P
cam_CSI0_D3_N: U1.30(CSI0_D3-) ; off-sheet cam_CSI0_D3_N
cam_CSI0_D3_P: U1.31(CSI0_D3+) ; off-sheet cam_CSI0_D3_P
GPIO1_0: U1.9(GPIO[0]) ; off-sheet GPIO1_0
GPIO1_1: U1.10(GPIO[1]) ; off-sheet GPIO1_1
GPIO1_2: U1.14(GPIO[2]) ; off-sheet GPIO1_2
GPIO1_3: U1.15(GPIO[3]) ; off-sheet GPIO1_3
I2C_SCL_UB960: U1.12(I2C_SCL) ; off-sheet I2C_SCL_UB960
I2C_SDA_UB960: U1.11(I2C_SDA) ; off-sheet I2C_SDA_UB960
INTB_CAM: R186.1 U1.6(INTB) ; off-sheet INTB_CAM
LPTX1_N: C41.1 U1.57(LPTXN)
LPTX1_P: C35.1 U1.56(LPTXP)
PDB_UB960_cam: R22.2 ; off-sheet PDB_UB960_cam
SYNC_CAMERA: U1.17(GPIO[4]) ; off-sheet SYNC_CAMERA
UB960_CLK_CAM: U1.5(REFCLOCK) ; off-sheet UB960_CLK_CAM
VDD18_P0_CAM: C37.1 C38.1 C39.1 C40.1 L6.2 U1.48(VDD18_P0)
VDD18_P1_CAM: C43.1 C44.1 C45.1 C46.1 L7.2 U1.47(VDD18_P1)
VDD18_P2_CAM: C48.1 C49.1 C50.1 C51.1 L8.2 U1.1(VDD18_P3)
VDD18_P3_CAM: C53.1 C54.1 C55.1 C56.1 L9.2 U1.2(VDD18_P2)
VDD18A_CAM: C22.1 C23.1 C24.1 C25.1 L4.2 U1.32(VDD18A)
VDDCSI_1V1_CAM: C8.1 C9.1 C10.1 C11.1 C12.1 L2.2 U1.21(VDD_CSI0) U1.33(VDD_CSI1)
VDDFPD_1V1_CAM: C14.1 C15.1 C16.1 C17.1 C18.1 L3.2 U1.52(VDD_FPD1) U1.61(VDD_FPD2)
VDDIO_CAM: C58.1 C59.1 C60.1 C61.1 L10.2 U1.16(VDDIO)
VDDL_1V1_CAM: C2.1 C3.1 C4.1 C5.1 C6.1 L1.2 U1.13(VDDL1) U1.44(VDDL2)
NetC19_1: C19.1 R21.1 R25.2 U1.46(IDX)
NetC20_1: C20.1 R22.1 R26.1 U1.3(PDB)
NetC26_1: C26.1 S4.1(A1) S4.2(A2) S4.3(A3) S4.4(A4) U1.45(MODE)
NetC35_2: C35.2 R29.1 TP2.1
NetC41_2: C41.2 R29.2 TP1.1
NetR23_1: R23.1 S4.8(B1)
NetR24_1: R24.1 S4.7(B2)
NetR27_1: R27.1 S4.6(B3)
NetR28_1: R28.1 S4.5(B4)
NetR30_2: R30.2 U1.4(TESTEN)

Not connected (* = marked no-connect by the designer): U1 7(I2C_SDA2) 8(I2C_SCL2) 18(GPIO[5]) 19(GPIO[6]) 20(GPIO[7]) 34(CSI1_CLK-) 35(CSI1_CLK+) 36(CSI1_D0-) 37(CSI1_D0+) 38(CSI1_D1-) 39(CSI1_D1+) 40(CSI1_D2-) 41(CSI1_D2+) 42(CSI1_D3-) 43(CSI1_D3+)

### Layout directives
differential pair: cam_0_n, cam_0_p, cam_1_n, cam_1_p, cam_2_n, cam_2_p, cam_3_n, cam_3_p, cam_CSI0_CLK_N, cam_CSI0_CLK_P, cam_CSI0_D0_N, cam_CSI0_D0_P, cam_CSI0_D1_N, cam_CSI0_D1_P, cam_CSI0_D2_N, cam_CSI0_D2_P, cam_CSI0_D3_N, cam_CSI0_D3_P, LPTX1_N, LPTX1_P

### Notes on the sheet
- REV B/E3
- I2C ID: 0x3D
- Coax / Twisted Pair
- Mode selection
- (near R186) REV B/E3

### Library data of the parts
C1 C2 C7 C8 C13 C14 C21 C22 C27 C28 C36 C37 C42 C43 C47 C48 C52 C53 C57 C58 = CL21A106KAFN3NE: CAP, CERM, 10 µF, 25 V, +/- 10%, X5R, 0805; Manufacturer: Samsung; Polarized: N; CompType: Capacitor; Value: 10uF; U/M: EA; Cap_F: 0.00001; Tolerance_%: 10; Value1: Unknown; VDC_V: 25; Value2: 25V; TaMin_C: -55; TaMax_C: 85; Cap_Case: 0805
C3 C9 C15 C23 C29 C38 C44 C49 C54 C59 = C1005JB1V105K050BC: CAP, CERM, 1 µF, 35 V, +/- 10%, JB, 0402; Manufacturer: TDK; Polarized: N; CompType: Capacitor; Value: 1uF; U/M: EA; Cap_F: 0.000001; Tolerance_%: 10; Value1: Unknown; VDC_V: 35; Value2: 35V; TaMin_C: -25; TaMax_C: 85
C4 C10 C16 C19 C24 C26 C30 C39 C45 C50 C55 C60 = GCM155R71H104KE02D: CAP, CERM, 0.1 µF, 50 V, +/- 10%, X7R, AEC-Q200 Grade 1, 0402; Manufacturer: MuRata; Polarized: N; CompType: Capacitor; Value: 0.1uF; U/M: EA; Cap_F: 0.0000001; Tolerance_%: 10; Value1: Unknown; VDC_V: 50; Value2: 50V; TaMin_C: -55; TaMax_C: 125; SizeArea_mm2: 0.5; SizeAreaWB_mm2: 3; SizeX_mm: 1; SizeZ_mm: 0.6; AEC Category: Q200; AEC Qualified: Y
C5 C6 C11 C12 C17 C18 C25 C31-C34 C40 C46 C51 C56 C61 = GCM155R71H103KA55D: CAP, CERM, 0.01uF, 50V, +/-10%, C0G/NP0, 0402; Manufacturer: MuRata; Polarized: N; CompType: Capacitor; U/M: EA; Cap_F: 0.00000001; Tolerance_%: 10; Value1: Unknown; VDC_V: 50; TaMin_C: -55; TaMax_C: 125
C20 = CL21A106KAFN3NE: CAP, CERM, 10 µF, 25 V, +/- 10%, X5R, 0805; Manufacturer: Samsung Electro-Mechanics; Polarized: N; CompType: Capacitor; Value: 10uF; U/M: EA; Cap_F: 0.00001; Tolerance_%: 10; Value1: Unknown; VDC_V: 25; Value2: 25V; TaMin_C: -55; TaMax_C: 85; Cap_Case: 0805; SizeArea_mm2: 2.5; SizeAreaWB_mm2: 6.75; SizeX_mm: 2; SizeY_mm: 1.25; SizeZ_mm: 1.45; AEC Category: Q200
C35 C41 = CGA2B3X7R1H333K050BB: CAP, CERM, 0.033 µF, 50 V, +/- 10%, X7R, AEC-Q200 Grade 1, 0402; Manufacturer: TDK; Polarized: N; CompType: Capacitor; Value: 0.033uF; U/M: EA; Cap_F: 0.000000033; Tolerance_%: 10; Value1: Unknown; VDC_V: 50; Value2: 50V; TaMin_C: -55; TaMax_C: 125; AEC Category: Q200; AEC Qualified: Y; AEC Grade: 1
L1-L3 L5-L9 = BLM18SG331TN1D: 1.5A Ferrite Bead, 330 ohm @ 100MHz, SMD; Manufacturer: MuRata; Imax_A: 3; DCR_ohm: 25milliiohm; Value1: 25 milliohm; Value2: 3A; ZTyp@100MHz_Ohm: 120; U/M: EA
L4 L10 = BLM18SG121TN1D: Ferrite Bead, 120 ohm @ 100 MHz, 3 A, 0603; Manufacturer: MuRata; Imax_A: 3; DCR_ohm: 0.025; Value1: 0.025 ohm; Value2: 3A; ZTyp@100MHz_Ohm: 120
R21 R23 = CRCW040213K3FKED: RES, 13.3 k, 1%, 0.063 W, 0402; Manufacturer: Vishay-Dale; CompType: Resistor; Value: 13.3k; Res_ohm: 13300; Value_Code: 13k3; Tolerance_%: 1; Power_W: 0.063; Value2: 0.063W; VDC_V: 50; TempCo: 100 ppm/C; EIA_Code: E96; U/M: EA; AEC Category: Q200
R22 = CRCW0402487RFKED: RES, 487, 1%, 0.063 W, 0402; Manufacturer: Vishay-Dale; CompType: Resistor; Value: 487; Value_Code: 487R; Tolerance_%: 1; Power_W: 0.063; Value2: 0.063W; VDC_V: 50; TempCo: 100 ppm/C; EIA_Code: E96; U/M: EA; AEC Category: Q200; SizeArea_mm2: 0.5; SizeZ_mm: 0.6
R24 = CRCW040282K5FKED: RES, 82.5 k, 1%, 0.063 W, 0402; Manufacturer: Vishay-Dale; CompType: Resistor; Value: 82.5k; Res_ohm: 82500; Value_Code: 82k5; Tolerance_%: 1; Power_W: 0.063; Value2: 0.063W; VDC_V: 50; TempCo: 100 ppm/C; EIA_Code: E96; U/M: EA; AEC Category: Q200
R25 R27 = CRCW040240K2FKED: RES, 40.2 k, 1%, 0.063 W, 0402; Manufacturer: Vishay-Dale; CompType: Resistor; Value: 40.2k; Res_ohm: 40200; Value_Code: 40k2; Tolerance_%: 1; Power_W: 0.063; Value2: 0.063W; VDC_V: 50; TempCo: 100 ppm/C; EIA_Code: E96; U/M: EA; AEC Category: Q200
R26 R186 = CRCW040210K0JNED: RES, 10 k, 5%, 0.063 W, 0402; Manufacturer: Vishay-Dale; CompType: Resistor; Value: 10k; Res_ohm: 10000; Value_Code: 10k0; Tolerance_%: 5; Power_W: 0.063; Value2: 0.063W; VDC_V: 50; TempCo: 200 ppm/C; EIA_Code: E24; U/M: EA; AEC Category: Q200; SizeArea_mm2: 0.5; SizeX_mm: 1; SizeZ_mm: 0.6
R28 = CRCW0402102KFKED: RES, 102 k, 1%, 0.063 W, 0402; Manufacturer: Vishay-Dale; CompType: Resistor; Value: 102k; Res_ohm: 102000; Tolerance_%: 1; Power_W: 0.063; Value2: 0.063W; VDC_V: 50; TempCo: 100 ppm/C; EIA_Code: E96; U/M: EA; AEC Category: Q200
R29 = CRCW0402100RFKED: RES, 100, 1%, 0.063 W, 0402; Manufacturer: Vishay-Dale; CompType: Resistor; Value: 100; Value_Code: 100R; Tolerance_%: 1; Power_W: 0.063; Value2: 0.063W; VDC_V: 50; TempCo: 100 ppm/C; EIA_Code: E96; U/M: EA; AEC Category: Q200
R30 = CRCW040210K0JNED: as R87 on sheet ADAS_SF_Power_Buck_3V3_1V8_1V1
S4 = 218-4LPST: as S3 on sheet ADAS_SF_Data_MSP430
TP1 TP2 = TP-025-SMT: Test Point, O.025"; Manufacturer: STD; Value: STD
U1 = DS90UB960TRGCRQ1: FPD-Link III Camera Hub Deserializer, RGC0064G; Alternate PartNumber: DS90UB960TRGCTQ1; Manufacturer: Texas Instruments; SymbolCreator: Altium; CompType: IC; U/M: EA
